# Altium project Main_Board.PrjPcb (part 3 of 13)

## Sheet LTC6952.SchDoc
size A3
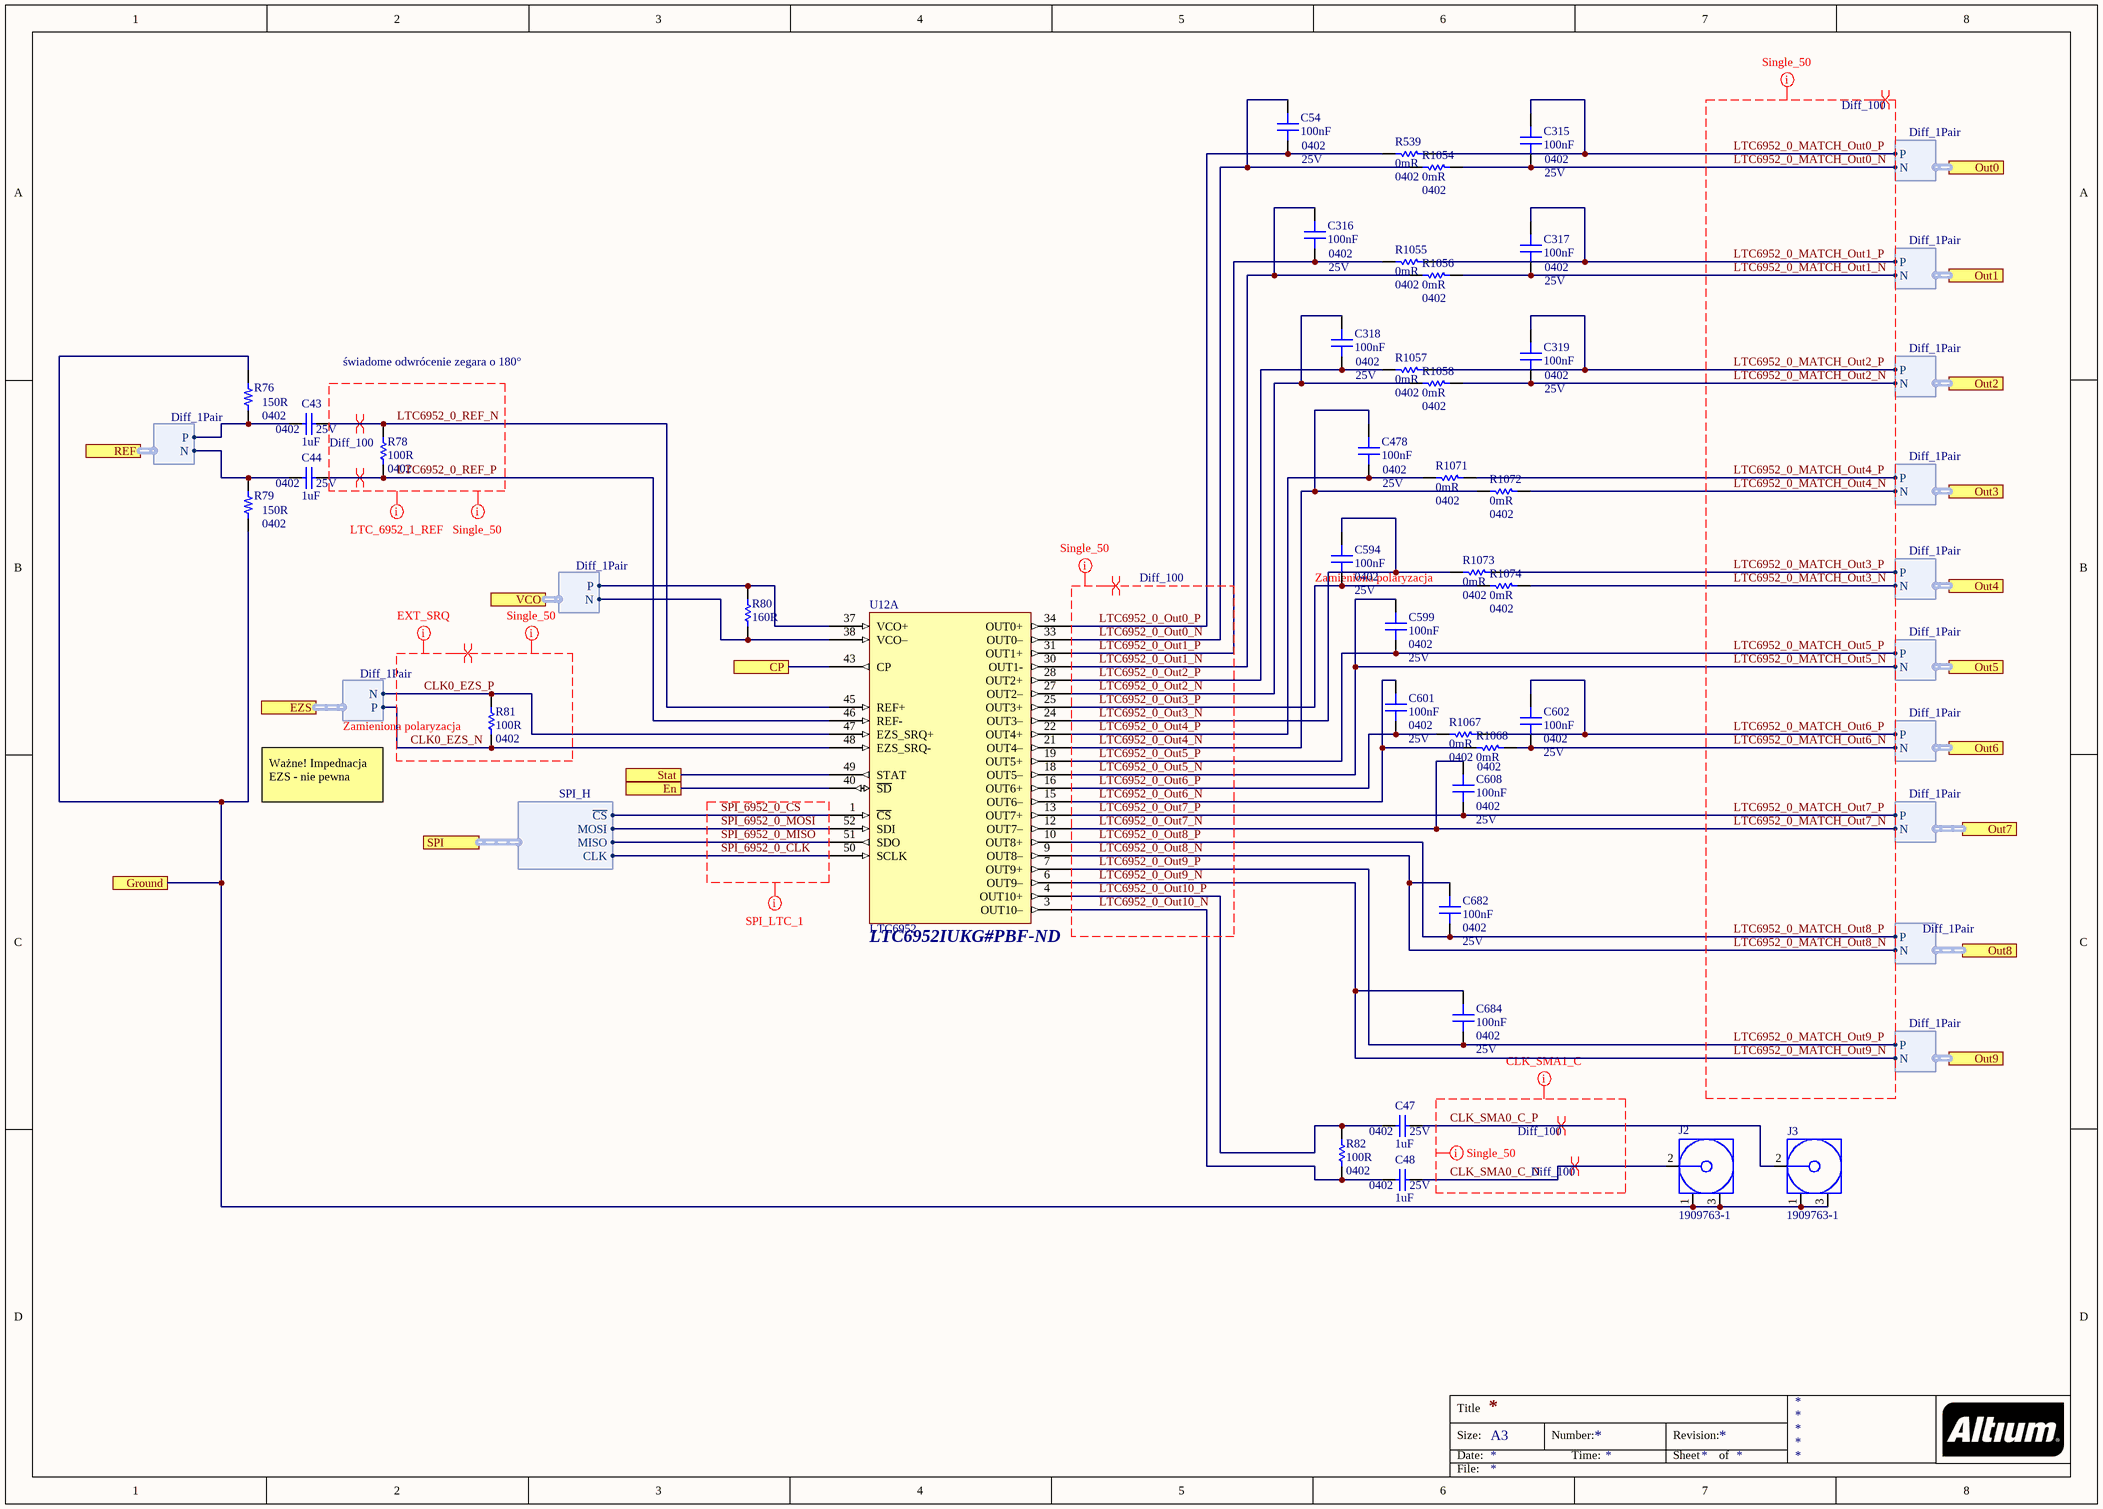
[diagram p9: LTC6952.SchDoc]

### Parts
(Parts that share a designator on the sheet are numbered #1, #2 ... from top to bottom, then left to right.)
C43  1uF  Case/Package: 0402  Voltage Rating: 25V  [CAP 0402/1005 KK]
C44  1uF  Case/Package: 0402  Voltage Rating: 25V  [CAP 0402/1005 KK]
C47  1uF  Case/Package: 0402  Voltage Rating: 25V  [CAP 0402/1005 KK]
C48  1uF  Case/Package: 0402  Voltage Rating: 25V  [CAP 0402/1005 KK]
C54  100nF  Case/Package: 0402  Voltage Rating: 25V  [CAP 0402/1005 KK]
C315  100nF  Case/Package: 0402  Voltage Rating: 25V  [CAP 0402/1005 KK]
C316  100nF  Case/Package: 0402  Voltage Rating: 25V  [CAP 0402/1005 KK]
C317  100nF  Case/Package: 0402  Voltage Rating: 25V  [CAP 0402/1005 KK]
C318  100nF  Case/Package: 0402  Voltage Rating: 25V  [CAP 0402/1005 KK]
C319  100nF  Case/Package: 0402  Voltage Rating: 25V  [CAP 0402/1005 KK]
C478#1  100nF  Case/Package: 0402  Voltage Rating: 25V  [CAP 0402/1005 KK]
C594  100nF  Case/Package: 0402  Voltage Rating: 25V  [CAP 0402/1005 KK]
C599  100nF  Case/Package: 0402  Voltage Rating: 25V  [CAP 0402/1005 KK]
C601  100nF  Case/Package: 0402  Voltage Rating: 25V  [CAP 0402/1005 KK]
C602  100nF  Case/Package: 0402  Voltage Rating: 25V  [CAP 0402/1005 KK]
C608  100nF  Case/Package: 0402  Voltage Rating: 25V  [CAP 0402/1005 KK]
C682  100nF  Case/Package: 0402  Voltage Rating: 25V  [CAP 0402/1005 KK]
C684  100nF  Case/Package: 0402  Voltage Rating: 25V  [CAP 0402/1005 KK]
J2  1909763-1  [TECO-1909763-1_V]
J3  1909763-1  [TECO-1909763-1_V]
R76  150R  Case/Package: 0402  [RES 0402/1005 RF KK]
R78  100R  Case/Package: 0402  [RES 0402/1005 RF KK]
R79  150R  Case/Package: 0402  [RES 0402/1005 RF KK]
R80  160R  [RES 0402/1005 RF KK]
R81  100R  Case/Package: 0402  [RES 0402/1005 RF KK]
R82  100R  Case/Package: 0402  [RES 0402/1005 RF KK]
R539  0mR  Case/Package: 0402  [RES 0402/1005 RF KK]
R1054  0mR  Case/Package: 0402  [RES 0402/1005 RF KK]
R1055  0mR  Case/Package: 0402  [RES 0402/1005 RF KK]
R1056  0mR  Case/Package: 0402  [RES 0402/1005 RF KK]
R1057  0mR  Case/Package: 0402  [RES 0402/1005 RF KK]
R1058  0mR  Case/Package: 0402  [RES 0402/1005 RF KK]
R1067  0mR  Case/Package: 0402  [RES 0402/1005 RF KK]
R1068  0mR  Case/Package: 0402  [RES 0402/1005 RF KK]
R1071  0mR  Case/Package: 0402  [RES 0402/1005 RF KK]
R1072  0mR  Case/Package: 0402  [RES 0402/1005 RF KK]
R1073  0mR  Case/Package: 0402  [RES 0402/1005 RF KK]
R1074  0mR  Case/Package: 0402  [RES 0402/1005 RF KK]
U12  LTC6952  Supplier Part Number 1: LTC6952IUKG#PBF-ND  [LTC6952]  (part A of 2)

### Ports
CP, En, EZS (harness Diff_1Pair), Ground, Out0 (harness Diff_1Pair), Out1 (harness Diff_1Pair), Out2 (harness Diff_1Pair), Out3 (harness Diff_1Pair), Out4 (harness Diff_1Pair), Out5 (harness Diff_1Pair), Out6 (harness Diff_1Pair), Out7 (harness Diff_1Pair), Out8 (harness Diff_1Pair), Out9 (harness Diff_1Pair), REF (harness Diff_1Pair), SPI (harness SPI_H), Stat, VCO (harness Diff_1Pair)

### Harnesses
SPI_H: CLK, MISO, MOSI, ~{CS}
Diff_1Pair: N, P

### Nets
AGND: J2.1 J2.3 J3.1 J3.3 R76.2 R79.1 ; port Ground
CLK0_EZS_N: R81.1 U12.48(EZS_SRQ-) ; port EZS.P
CLK0_EZS_P: R81.2 U12.47(EZS_SRQ+) ; port EZS.N
CLK_SMA0_C_N: C48.1 J2.2
CLK_SMA0_C_P: C47.1 J3.2
Enable_CLK: U12.40(~{SD}) ; port En
LTC6952_0_MATCH_Out0_N: C315.1 R1054.1 ; port Out0.N
LTC6952_0_MATCH_Out0_P: C315.2 R539.1 ; port Out0.P
LTC6952_0_MATCH_Out1_N: C317.1 R1056.1 ; port Out1.N
LTC6952_0_MATCH_Out1_P: C317.2 R1055.1 ; port Out1.P
LTC6952_0_MATCH_Out2_N: C319.1 R1058.1 ; port Out2.N
LTC6952_0_MATCH_Out2_P: C319.2 R1057.1 ; port Out2.P
LTC6952_0_MATCH_Out3_N: R1074.1 ; port Out4.N
LTC6952_0_MATCH_Out3_P: R1073.1 ; port Out4.P
LTC6952_0_MATCH_Out4_N: R1072.2 ; port Out3.N
LTC6952_0_MATCH_Out4_P: R1071.2 ; port Out3.P
LTC6952_0_MATCH_Out5_N: C599.1 U12.18(OUT5–) ; port Out5.N  [also labelled LTC6952_0_Out5_N]
LTC6952_0_MATCH_Out5_P: C599.2 U12.19(OUT5+) ; port Out5.P  [also labelled LTC6952_0_Out5_P]
LTC6952_0_MATCH_Out6_N: C602.2 R1068.1 ; port Out6.N
LTC6952_0_MATCH_Out6_P: C602.1 R1067.1 ; port Out6.P
LTC6952_0_MATCH_Out7_N: C608.1 U12.12(OUT7–) ; port Out7.N  [also labelled LTC6952_0_Out7_N]
LTC6952_0_MATCH_Out7_P: C608.2 U12.13(OUT7+) ; port Out7.P  [also labelled LTC6952_0_Out7_P]
LTC6952_0_MATCH_Out8_N: C682.1 U12.9(OUT8–) ; port Out8.N  [also labelled LTC6952_0_Out8_N]
LTC6952_0_MATCH_Out8_P: C682.2 U12.10(OUT8+) ; port Out8.P  [also labelled LTC6952_0_Out8_P]
LTC6952_0_MATCH_Out9_N: C684.1 U12.6(OUT9–) ; port Out9.N  [also labelled LTC6952_0_Out9_N]
LTC6952_0_MATCH_Out9_P: C684.2 U12.7(OUT9+) ; port Out9.P  [also labelled LTC6952_0_Out9_P]
LTC6952_0_Out0_N: C54.2 R1054.2 U12.33(OUT0–)
LTC6952_0_Out0_P: C54.1 R539.2 U12.34(OUT0+)
LTC6952_0_Out1_N: C316.2 R1056.2 U12.30(OUT1-)
LTC6952_0_Out1_P: C316.1 R1055.2 U12.31(OUT1+)
LTC6952_0_Out2_N: C318.2 R1058.2 U12.27(OUT2–)
LTC6952_0_Out2_P: C318.1 R1057.2 U12.28(OUT2+)
LTC6952_0_Out3_N: C594.1 R1073.2 U12.24(OUT3–)
LTC6952_0_Out3_P: C594.2 R1074.2 U12.25(OUT3+)
LTC6952_0_Out4_N: C478#1.2 R1072.1 U12.21(OUT4–)
LTC6952_0_Out4_P: C478#1.1 R1071.1 U12.22(OUT4+)
LTC6952_0_Out6_N: C601.1 R1068.2 U12.15(OUT6–)
LTC6952_0_Out6_P: C601.2 R1067.2 U12.16(OUT6+)
LTC6952_0_Out10_N: C48.2 R82.1 U12.3(OUT10–)
LTC6952_0_Out10_P: C47.2 R82.2 U12.4(OUT10+)
LTC6952_0_REF_N: C43.1 R78.2 U12.45(REF+)
LTC6952_0_REF_P: C44.1 R78.1 U12.46(REF-)
LTC6952_1_CP_Out: U12.43(CP) ; port CP
LTC6952_1_Temp: U12.49(STAT) ; port Stat
LTC6952_1_VCO_N: R80.2 U12.37(VCO+) ; port VCO.P
LTC6952_1_VCO_P: R80.1 U12.38(VCO–) ; port VCO.N
Si53323_2_Q1_N: C44.2 R79.2 ; port REF.N
Si53323_2_Q1_P: C43.2 R76.1 ; port REF.P
SPI_6952_0_CLK: U12.50(SCLK) ; port SPI.CLK  [project net CLK0_SPI.CLK]
SPI_6952_0_CS: U12.1(~{CS}) ; port SPI.~{CS}  [project net CLK0_SPI.~{CS}]
SPI_6952_0_MISO: U12.51(SDO) ; port SPI.MISO  [project net CLK0_SPI.MISO]
SPI_6952_0_MOSI: U12.52(SDI) ; port SPI.MOSI  [project net CLK0_SPI.MOSI]

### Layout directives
differential pair; differential pair class Diff_100: CLK0_EZS_N, CLK0_EZS_P, CLK_SMA0_C_N, CLK_SMA0_C_P, LTC6952_0_MATCH_Out0_N, LTC6952_0_MATCH_Out0_P, LTC6952_0_MATCH_Out1_N, LTC6952_0_MATCH_Out1_P, LTC6952_0_MATCH_Out2_N, LTC6952_0_MATCH_Out2_P, LTC6952_0_MATCH_Out3_N, LTC6952_0_MATCH_Out3_P, LTC6952_0_MATCH_Out4_N, LTC6952_0_MATCH_Out4_P, LTC6952_0_MATCH_Out5_N, LTC6952_0_MATCH_Out5_P, LTC6952_0_MATCH_Out6_N, LTC6952_0_MATCH_Out6_P, LTC6952_0_MATCH_Out7_N, LTC6952_0_MATCH_Out7_P, LTC6952_0_MATCH_Out8_N, LTC6952_0_MATCH_Out8_P, LTC6952_0_MATCH_Out9_N, LTC6952_0_MATCH_Out9_P, LTC6952_0_Out0_N, LTC6952_0_Out0_P, LTC6952_0_Out1_N, LTC6952_0_Out1_P, LTC6952_0_Out2_N, LTC6952_0_Out2_P, LTC6952_0_Out3_N, LTC6952_0_Out3_P, LTC6952_0_Out4_N, LTC6952_0_Out4_P, LTC6952_0_Out5_N, LTC6952_0_Out5_P, LTC6952_0_Out6_N, LTC6952_0_Out6_P, LTC6952_0_Out7_N, LTC6952_0_Out7_P, LTC6952_0_Out8_N, LTC6952_0_Out8_P, LTC6952_0_Out9_N, LTC6952_0_Out9_P, LTC6952_0_Out10_N, LTC6952_0_Out10_P, LTC6952_0_REF_N, LTC6952_0_REF_P
net class Single_50: CLK0_EZS_N, CLK0_EZS_P, CLK_SMA0_C_N, CLK_SMA0_C_P, LTC6952_0_MATCH_Out0_N, LTC6952_0_MATCH_Out0_P, LTC6952_0_MATCH_Out1_N, LTC6952_0_MATCH_Out1_P, LTC6952_0_MATCH_Out2_N, LTC6952_0_MATCH_Out2_P, LTC6952_0_MATCH_Out3_N, LTC6952_0_MATCH_Out3_P, LTC6952_0_MATCH_Out4_N, LTC6952_0_MATCH_Out4_P, LTC6952_0_MATCH_Out5_N, LTC6952_0_MATCH_Out5_P, LTC6952_0_MATCH_Out6_N, LTC6952_0_MATCH_Out6_P, LTC6952_0_MATCH_Out7_N, LTC6952_0_MATCH_Out7_P, LTC6952_0_MATCH_Out8_N, LTC6952_0_MATCH_Out8_P, LTC6952_0_MATCH_Out9_N, LTC6952_0_MATCH_Out9_P, LTC6952_0_Out0_N, LTC6952_0_Out0_P, LTC6952_0_Out1_N, LTC6952_0_Out1_P, LTC6952_0_Out2_N, LTC6952_0_Out2_P, LTC6952_0_Out3_N, LTC6952_0_Out3_P, LTC6952_0_Out4_N, LTC6952_0_Out4_P, LTC6952_0_Out5_N, LTC6952_0_Out5_P, LTC6952_0_Out6_N, LTC6952_0_Out6_P, LTC6952_0_Out7_N, LTC6952_0_Out7_P, LTC6952_0_Out8_N, LTC6952_0_Out8_P, LTC6952_0_Out9_N, LTC6952_0_Out9_P, LTC6952_0_Out10_N, LTC6952_0_Out10_P, LTC6952_0_REF_N, LTC6952_0_REF_P
net class CLK_SMA1_C: CLK_SMA0_C_N, CLK_SMA0_C_P
net class LTC_6952_1_REF: LTC6952_0_REF_N, LTC6952_0_REF_P
net class EXT_SRQ: CLK0_EZS_N, CLK0_EZS_P
net class SPI_LTC_1: SPI_6952_0_CLK, SPI_6952_0_CS, SPI_6952_0_MISO, SPI_6952_0_MOSI

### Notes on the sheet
- świadome odwrócenie zegara o 180°
- (near C594) Zamieniona polaryzacja
- (near R81) Zamieniona polaryzacja
- Ważne! Impednacja EZS - nie pewna

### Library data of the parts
C43 C44 C47 C48 = Capacitor: MURATA - GRT155R61E105KE01D - SMD Multilayer Ceramic Capacitor, 1 µF, 25 V, 0402 [1005 Metric], ± 10%, X5R, GRT Series - SMD Multilayer Ceramic Capacitor, 1 µF, 25 V, 0402 [1005 Metric], ± 10%, X5R, GRT Series
C54 C315-C319 C478#1 C594 C599 C601 C602 C608 C682 C684 = Capacitor: Manufacturer: Murata; Manufacturer Part Number: GRM155R71E104KE14J; Tolerance: 10%; Dielectric: X7R
J2 J3 = 1909763-1: Ultra Miniature Coaxial Connector Jack, 60 V, 50 Ohm, -40 to 90 degC, RoHS, Tape and Reel; Brand: TE Connectivity / AMP; Maximum Frequency: 6 GHz; Gender: Jack (Female); Body Material: Liquid Crystal Polymer (LCP); RF Series: UMCC; Impedance: 50 Ohms
R76 R79 = Resistor: RES SMD 150 OHM 1% 1/10W 0402; Manufacturer: Panasonic; Manufacturer Part Number: ERJ-2RKF1500X; Temperature Coefficient: 100ppm/°C; Power Rating: 100mW; Voltage Rating: 50V
R78 R81 R82 = Resistor: RES SMD 100 OHM 1% 1/16W 0402; Manufacturer: Yageo; Manufacturer Part Number: RC0402FR-07100RL; Power Rating: 62.5mW; Voltage Rating: 50V; Temperature Coefficient: 100ppm/°C
R80 = Resistor: Res Thick Film 0402 160 Ohm 1% 1/16W 100ppm/C Molded SMD SMD Paper T/R; Manufacturer: Stackpole Electronics; Manufacturer Part Number: RMCF0402FT160R; Temperature Coefficient: 100ppm/°C
R539 R1054-R1058 R1067 R1068 R1071-R1074 = Resistor: Manufacturer 1: Yageo; Manufacturer Part Number 1: RC0402JR-070RL; Power Rating: 62.5mW; Tolerance: 5%; Voltage Rating: 50V; Max Power Dissipation: 63mW; Temperature Coefficient: 200ppm/°C
U12 = LTC6952: Dystrybutor Zegarów; Manufacturer: Analog Devices; Manufacturer Part Number: LTC6952IUKG#PBF

## Sheet Ultrascale+_02.SchDoc: Ultrascale+_02
size A3; Organization: Altium Limited; Address1: L3, 12a Rodborough Rd; Address2: Frenchs Forest; Address3: NSW; Address4: Australia 2086
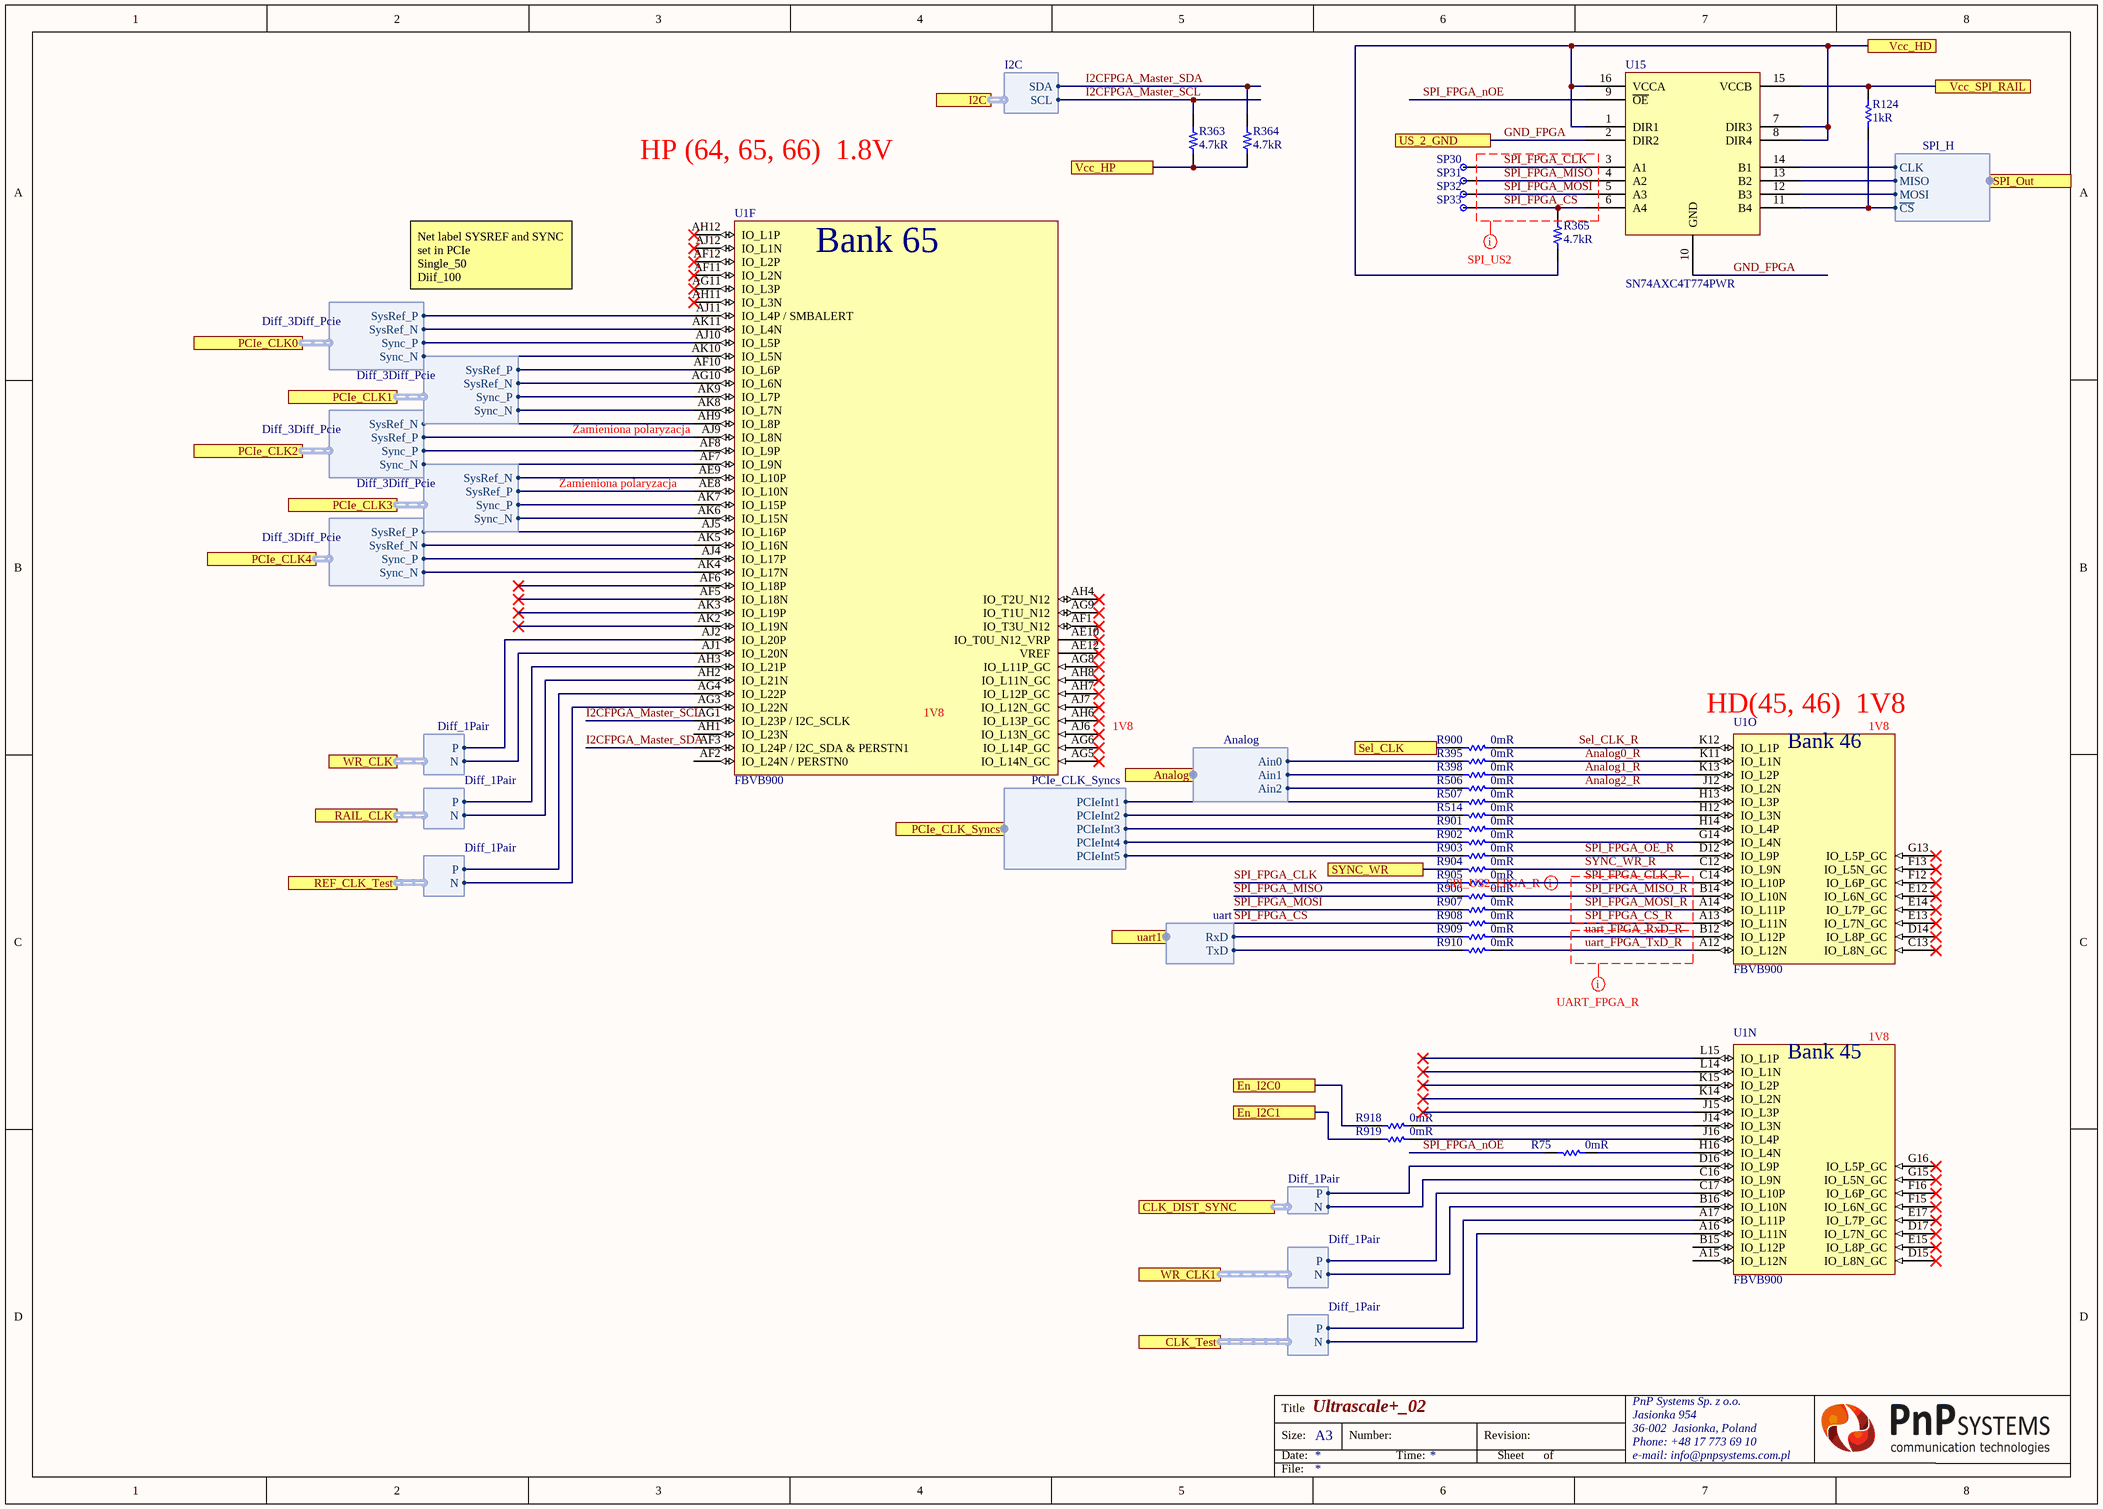
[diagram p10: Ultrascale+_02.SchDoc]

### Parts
R75  0mR  [RES 0402/1005 RF KK]
R124  1kR  [RES 0402/1005 RF KK]
R363  4.7kR  [RES 0402/1005 RF KK]
R364  4.7kR  [RES 0402/1005 RF KK]
R365  4.7kR  [RES 0402/1005 RF KK]
R395  0mR  [RES 0402/1005 RF KK]
R398  0mR  [RES 0402/1005 RF KK]
R506  0mR  [RES 0402/1005 RF KK]
R507  0mR  [RES 0402/1005 RF KK]
R514  0mR  [RES 0402/1005 RF KK]
R900  0mR  [RES 0402/1005 RF KK]
R901  0mR  [RES 0402/1005 RF KK]
R902  0mR  [RES 0402/1005 RF KK]
R903  0mR  [RES 0402/1005 RF KK]
R904  0mR  [RES 0402/1005 RF KK]
R905  0mR  [RES 0402/1005 RF KK]
R906  0mR  [RES 0402/1005 RF KK]
R907  0mR  [RES 0402/1005 RF KK]
R908  0mR  [RES 0402/1005 RF KK]
R909  0mR  [RES 0402/1005 RF KK]
R910  0mR  [RES 0402/1005 RF KK]
R918  0mR  [RES 0402/1005 RF KK]
R919  0mR  [RES 0402/1005 RF KK]
SP30  SP  [MeasureTP]  (value not drawn)
SP31  SP  [MeasureTP]  (value not drawn)
SP32  SP  [MeasureTP]  (value not drawn)
SP33  SP  [MeasureTP]  (value not drawn)
U1  FBVB900  [FBVB900 XX]  (parts F,N,O of 23)
U15  SN74AXC4T774PWR  [SN74AXC4T774PWR]

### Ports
Analog (harness Analog), CLK_DIST_SYNC (harness Diff_1Pair), CLK_Test (harness Diff_1Pair), En_I2C0, En_I2C1, I2C (harness I2C), PCIe_CLK0 (harness Diff_3Diff_Pcie), PCIe_CLK1 (harness Diff_3Diff_Pcie), PCIe_CLK2 (harness Diff_3Diff_Pcie), PCIe_CLK3 (harness Diff_3Diff_Pcie), PCIe_CLK4 (harness Diff_3Diff_Pcie), PCIe_CLK_Syncs (harness PCIe_CLK_Syncs), RAIL_CLK (harness Diff_1Pair), REF_CLK_Test (harness Diff_1Pair), Sel_CLK, SPI_Out (harness SPI_H), SYNC_WR, uart1 (harness uart), US_2_GND, Vcc_HD, Vcc_HP, Vcc_SPI_RAIL, WR_CLK1 (harness Diff_1Pair), WR_CLK (harness Diff_1Pair)

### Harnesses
I2C: SDA, SCL
uart: RxD, TxD
Diff_1Pair: N, P
Diff_1Pair: P, N
SPI_H: CLK, MISO, MOSI, ~{CS}
Analog: Ain0, Ain1, Ain2
PCIe_CLK_Syncs: PCIeInt1, PCIeInt2, PCIeInt3, PCIeInt4, PCIeInt5
Diff_3Diff_Pcie: SysRef_N, SysRef_P, Sync_P, Sync_N

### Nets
GND_FPGA: U15.2(DIR2) U15.10(GND) ; port US_2_GND  [project net B503_Ground]
3V3_RAIL: R124.2 U15.15(VCCB) ; port Vcc_SPI_RAIL
Analog0_R: R395.1 U1.K11(IO_L1N)
Analog1_R: R398.1 U1.K13(IO_L2P)
Analog2_R: R506.1 U1.J12(IO_L2N)
CLK0_EZS_N: U1.D16(IO_L9P) ; port CLK_DIST_SYNC.P
CLK0_EZS_P: U1.C16(IO_L9N) ; port CLK_DIST_SYNC.N
D_05028_G0: R904.2 ; port SYNC_WR
I2CFPGA_Master_SCL: R363.2 U1.AG1(IO_L23P_/_I2C_SCLK) ; port I2C.SCL  [project net I2C_LS.SCL]
I2CFPGA_Master_SDA: R364.2 U1.AF3(IO_L24P_/_I2C_SDA_&_PERSTN1) ; port I2C.SDA  [project net I2C_LS.SDA]
LTC6952_1_MATCH_Out1_N: U1.AH2(IO_L21N) ; port RAIL_CLK.N
LTC6952_1_MATCH_Out1_P: U1.AH3(IO_L21P) ; port RAIL_CLK.P
LTC6952_1_Temp: R395.2 ; port Analog.Ain0
LTC6952_2_Temp: R398.2 ; port Analog.Ain1
LTC6952_3_Temp: R506.2 ; port Analog.Ain2
RF_SYSREF_TO_FPGA_N: U1.AK11(IO_L4N) ; port PCIe_CLK0.SysRef_N
RF_SYSREF_TO_FPGA_N: U1.AG10(IO_L6N) ; port PCIe_CLK1.SysRef_N  [a separate net that carries the same name]
RF_SYSREF_TO_FPGA_N: U1.AH9(IO_L8P) ; port PCIe_CLK2.SysRef_N  [a separate net that carries the same name]
RF_SYSREF_TO_FPGA_N: U1.AE9(IO_L10P) ; port PCIe_CLK3.SysRef_N  [a separate net that carries the same name]
RF_SYSREF_TO_FPGA_N: U1.AK5(IO_L16N) ; port PCIe_CLK4.SysRef_N  [a separate net that carries the same name]
RF_SYSREF_TO_FPGA_P: U1.AJ11(IO_L4P_/_SMBALERT) ; port PCIe_CLK0.SysRef_P
RF_SYSREF_TO_FPGA_P: U1.AF10(IO_L6P) ; port PCIe_CLK1.SysRef_P  [a separate net that carries the same name]
RF_SYSREF_TO_FPGA_P: U1.AJ9(IO_L8N) ; port PCIe_CLK2.SysRef_P  [a separate net that carries the same name]
RF_SYSREF_TO_FPGA_P: U1.AE8(IO_L10N) ; port PCIe_CLK3.SysRef_P  [a separate net that carries the same name]
RF_SYSREF_TO_FPGA_P: U1.AJ5(IO_L16P) ; port PCIe_CLK4.SysRef_P  [a separate net that carries the same name]
Sel_CLK_R: R900.1 U1.K12(IO_L1P)
SetClk_Si53323_2: R900.2 ; port Sel_CLK
Si53323_1_Q2_LVDS_N: U1.AG3(IO_L22N) ; port REF_CLK_Test.N
Si53323_1_Q2_LVDS_P: U1.AG4(IO_L22P) ; port REF_CLK_Test.P
Si53323_2_Q2_LVDS_N: U1.A16(IO_L11N) ; port CLK_Test.N
Si53323_2_Q2_LVDS_P: U1.A17(IO_L11P) ; port CLK_Test.P
SPI1_CLK: U15.14(B1) ; port SPI_Out.CLK
SPI1_CS: R124.1 U15.11(B4) ; port SPI_Out.~{CS}
SPI1_MISO: U15.13(B2) ; port SPI_Out.MISO
SPI1_MOSI: U15.12(B3) ; port SPI_Out.MOSI
SPI_FPGA_CLK: R905.2 SP30.1 U15.3(A1)
SPI_FPGA_CLK_R: R905.1 U1.C14(IO_L10P)
SPI_FPGA_CS: R365.2 R908.2 SP33.1 U15.6(A4)
SPI_FPGA_CS_R: R908.1 U1.A13(IO_L11N)
SPI_FPGA_MISO: R906.2 SP31.1 U15.4(A2)
SPI_FPGA_MISO_R: R906.1 U1.B14(IO_L10N)
SPI_FPGA_MOSI: R907.2 SP32.1 U15.5(A3)
SPI_FPGA_MOSI_R: R907.1 U1.A14(IO_L11P)
SPI_FPGA_nOE: R75.2 U15.9(~{OE})
SPI_FPGA_OE_R: R903.1 U1.D12(IO_L9P)
SYNC_N: U1.AK10(IO_L5N) ; port PCIe_CLK0.Sync_N
SYNC_N: U1.AK8(IO_L7N) ; port PCIe_CLK1.Sync_N  [a separate net that carries the same name]
SYNC_N: U1.AF7(IO_L9N) ; port PCIe_CLK2.Sync_N  [a separate net that carries the same name]
SYNC_N: U1.AK6(IO_L15N) ; port PCIe_CLK3.Sync_N  [a separate net that carries the same name]
SYNC_N: U1.AK4(IO_L17N) ; port PCIe_CLK4.Sync_N  [a separate net that carries the same name]
SYNC_P: U1.AJ10(IO_L5P) ; port PCIe_CLK0.Sync_P
SYNC_P: U1.AK9(IO_L7P) ; port PCIe_CLK1.Sync_P  [a separate net that carries the same name]
SYNC_P: U1.AF8(IO_L9P) ; port PCIe_CLK2.Sync_P  [a separate net that carries the same name]
SYNC_P: U1.AK7(IO_L15P) ; port PCIe_CLK3.Sync_P  [a separate net that carries the same name]
SYNC_P: U1.AJ4(IO_L17P) ; port PCIe_CLK4.Sync_P  [a separate net that carries the same name]
SYNC_WR_R: R904.1 U1.C12(IO_L9N)
uart_FPGA_RxD_R: R909.1 U1.B12(IO_L12P)
uart_FPGA_TxD_R: R910.1 U1.A12(IO_L12N)
US2_FTDI_UART1_RXD: R910.2 ; port uart1.TxD
US2_FTDI_UART1_TXD: R909.2 ; port uart1.RxD
US+_MGTVccAux: R363.1 R364.1 R365.1 U15.1(DIR1) U15.7(DIR3) U15.8(DIR4) U15.16(VCCA) ; port Vcc_HP, port Vcc_HD
WR_LMK_CLK_RC_HF1_N: U1.AJ1(IO_L20N) ; port WR_CLK.N
WR_LMK_CLK_RC_HF1_P: U1.AJ2(IO_L20P) ; port WR_CLK.P
WR_LMK_CLK_RC_HF2_N: U1.C17(IO_L10P) ; port WR_CLK1.P
WR_LMK_CLK_RC_HF2_P: U1.B16(IO_L10N) ; port WR_CLK1.N
NetJ1_PCIE0_20: R507.2 ; port PCIe_CLK_Syncs.PCIeInt1
NetJ1_PCIE1_20: R514.2 ; port PCIe_CLK_Syncs.PCIeInt2
NetJ1_PCIE2_20: R901.2 ; port PCIe_CLK_Syncs.PCIeInt3
NetJ1_PCIE3_20: R902.2 ; port PCIe_CLK_Syncs.PCIeInt4
NetJ1_PCIE4_20: R903.2 ; port PCIe_CLK_Syncs.PCIeInt5
NetR75_1: R75.1 U1.H16(IO_L4N)
NetR507_1: R507.1 U1.H13(IO_L3P)
NetR514_1: R514.1 U1.H12(IO_L3N)
NetR901_1: R901.1 U1.H14(IO_L4P)
NetR902_1: R902.1 U1.G14(IO_L4N)
NetR918_1: R918.1 U1.J14(IO_L3N)
NetR918_2: R918.2 ; port En_I2C0
NetR919_1: R919.1 U1.J16(IO_L4P)
NetR919_2: R919.2 ; port En_I2C1

Not connected (* = marked no-connect by the designer): U1 A15(IO_L12N) AE10(IO_T0U_N12_VRP)* AE12(VREF)* AF1(IO_T3U_N12)* AF2(IO_L24N_/_PERSTN0) AF5(IO_L18N)* AF6(IO_L18P)* AF11(IO_L2N)* AF12(IO_L2P)* AG5(IO_L14N_GC)* AG6(IO_L14P_GC)* AG8(IO_L11P_GC)* AG9(IO_T1U_N12)* AG11(IO_L3P)* AH1(IO_L23N) AH4(IO_T2U_N12)* AH6(IO_L13P_GC)* AH7(IO_L12P_GC)* AH8(IO_L11N_GC)* AH11(IO_L3N)* AH12(IO_L1P)* AJ6(IO_L13N_GC)* AJ7(IO_L12N_GC)* AJ12(IO_L1N)* AK2(IO_L19N)* AK3(IO_L19P)* B15(IO_L12P) C13(IO_L8N_GC)* D14(IO_L8P_GC)* D15(IO_L8N_GC)* D17(IO_L7N_GC)* E12(IO_L6N_GC)* E13(IO_L7N_GC)* E14(IO_L7P_GC)* E15(IO_L8P_GC)* E17(IO_L7P_GC)* F12(IO_L6P_GC)* F13(IO_L5N_GC)* F15(IO_L6N_GC)* F16(IO_L6P_GC)* G13(IO_L5P_GC)* G15(IO_L5N_GC)* G16(IO_L5P_GC)* J15(IO_L3P)* K14(IO_L2N)* K15(IO_L2P)* L14(IO_L1N)* L15(IO_L1P)*

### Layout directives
net class SPI_US2_R: SPI_FPGA_CLK, SPI_FPGA_CS, SPI_FPGA_MISO, SPI_FPGA_MOSI
net class SPI_US2_FPGA_R: SPI_FPGA_CLK_R
net class UART_FPGA_R: uart_FPGA_RxD_R, uart_FPGA_TxD_R

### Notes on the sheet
- HP (64, 65, 66)  1.8V
- Net label SYSREF and SYNC set in PCIe
  Single_50
  Diif_100
- (near U1) Zamieniona polaryzacja
- (near U1) 1V8
- (near U1) HD(45, 46)  1V8
- 1V8

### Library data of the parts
R75 R395 R398 R506 R507 R514 R900-R910 R918 R919 = Resistor: as R539 on sheet LTC6952
R124 = Resistor: PANASONIC - ERJ-2RKF1001X - SMD Chip Resistor, 0402 [1005 Metric], 1 kohm, ERJ2R Series, 50 V, Thick Film, 100 mW; Temperature Coefficient: 100ppm/°C; Tolerance: 1%; Voltage Rating (DC): 50V; Power Rating: 100mW
R363-R365 = Resistor: Manufacturer: Panasonic; Manufacturer Part Number: ERJ-2RKF4701X; Tolerance: 1%; Temperature Coefficient: 100ppm/°C; Power Rating: 100mW; Voltage Rating: 50V
U1 = FBVB900: FPGA Zynq UltraScale+ Family 192150 Cells 20nm Technology 0.85V 900-Pin FCBGA Tray; Manufacturer Part Number: XCZU4CG-1FBVB900E; Manufacturer: Xilinx; Peripherals: WDT,DMA; Interface: I2C,SPI,USB,Ethernet,MMC,SDIO,SD,UART,USART,EBI/EMI; Core Architecture: ARM; RAM Size: 256KB; Frequency: 500MHz; Number of I/Os: 204
U15 = SN74AXC4T774PWR: Manufacturer 1: Texas Instruments

## Sheet JESD204_B_or_C.SchDoc: JESD204_B
size A3; Organization: Altium Limited; Address1: L3, 12a Rodborough Rd; Address2: Frenchs Forest; Address3: NSW; Address4: Australia 2086
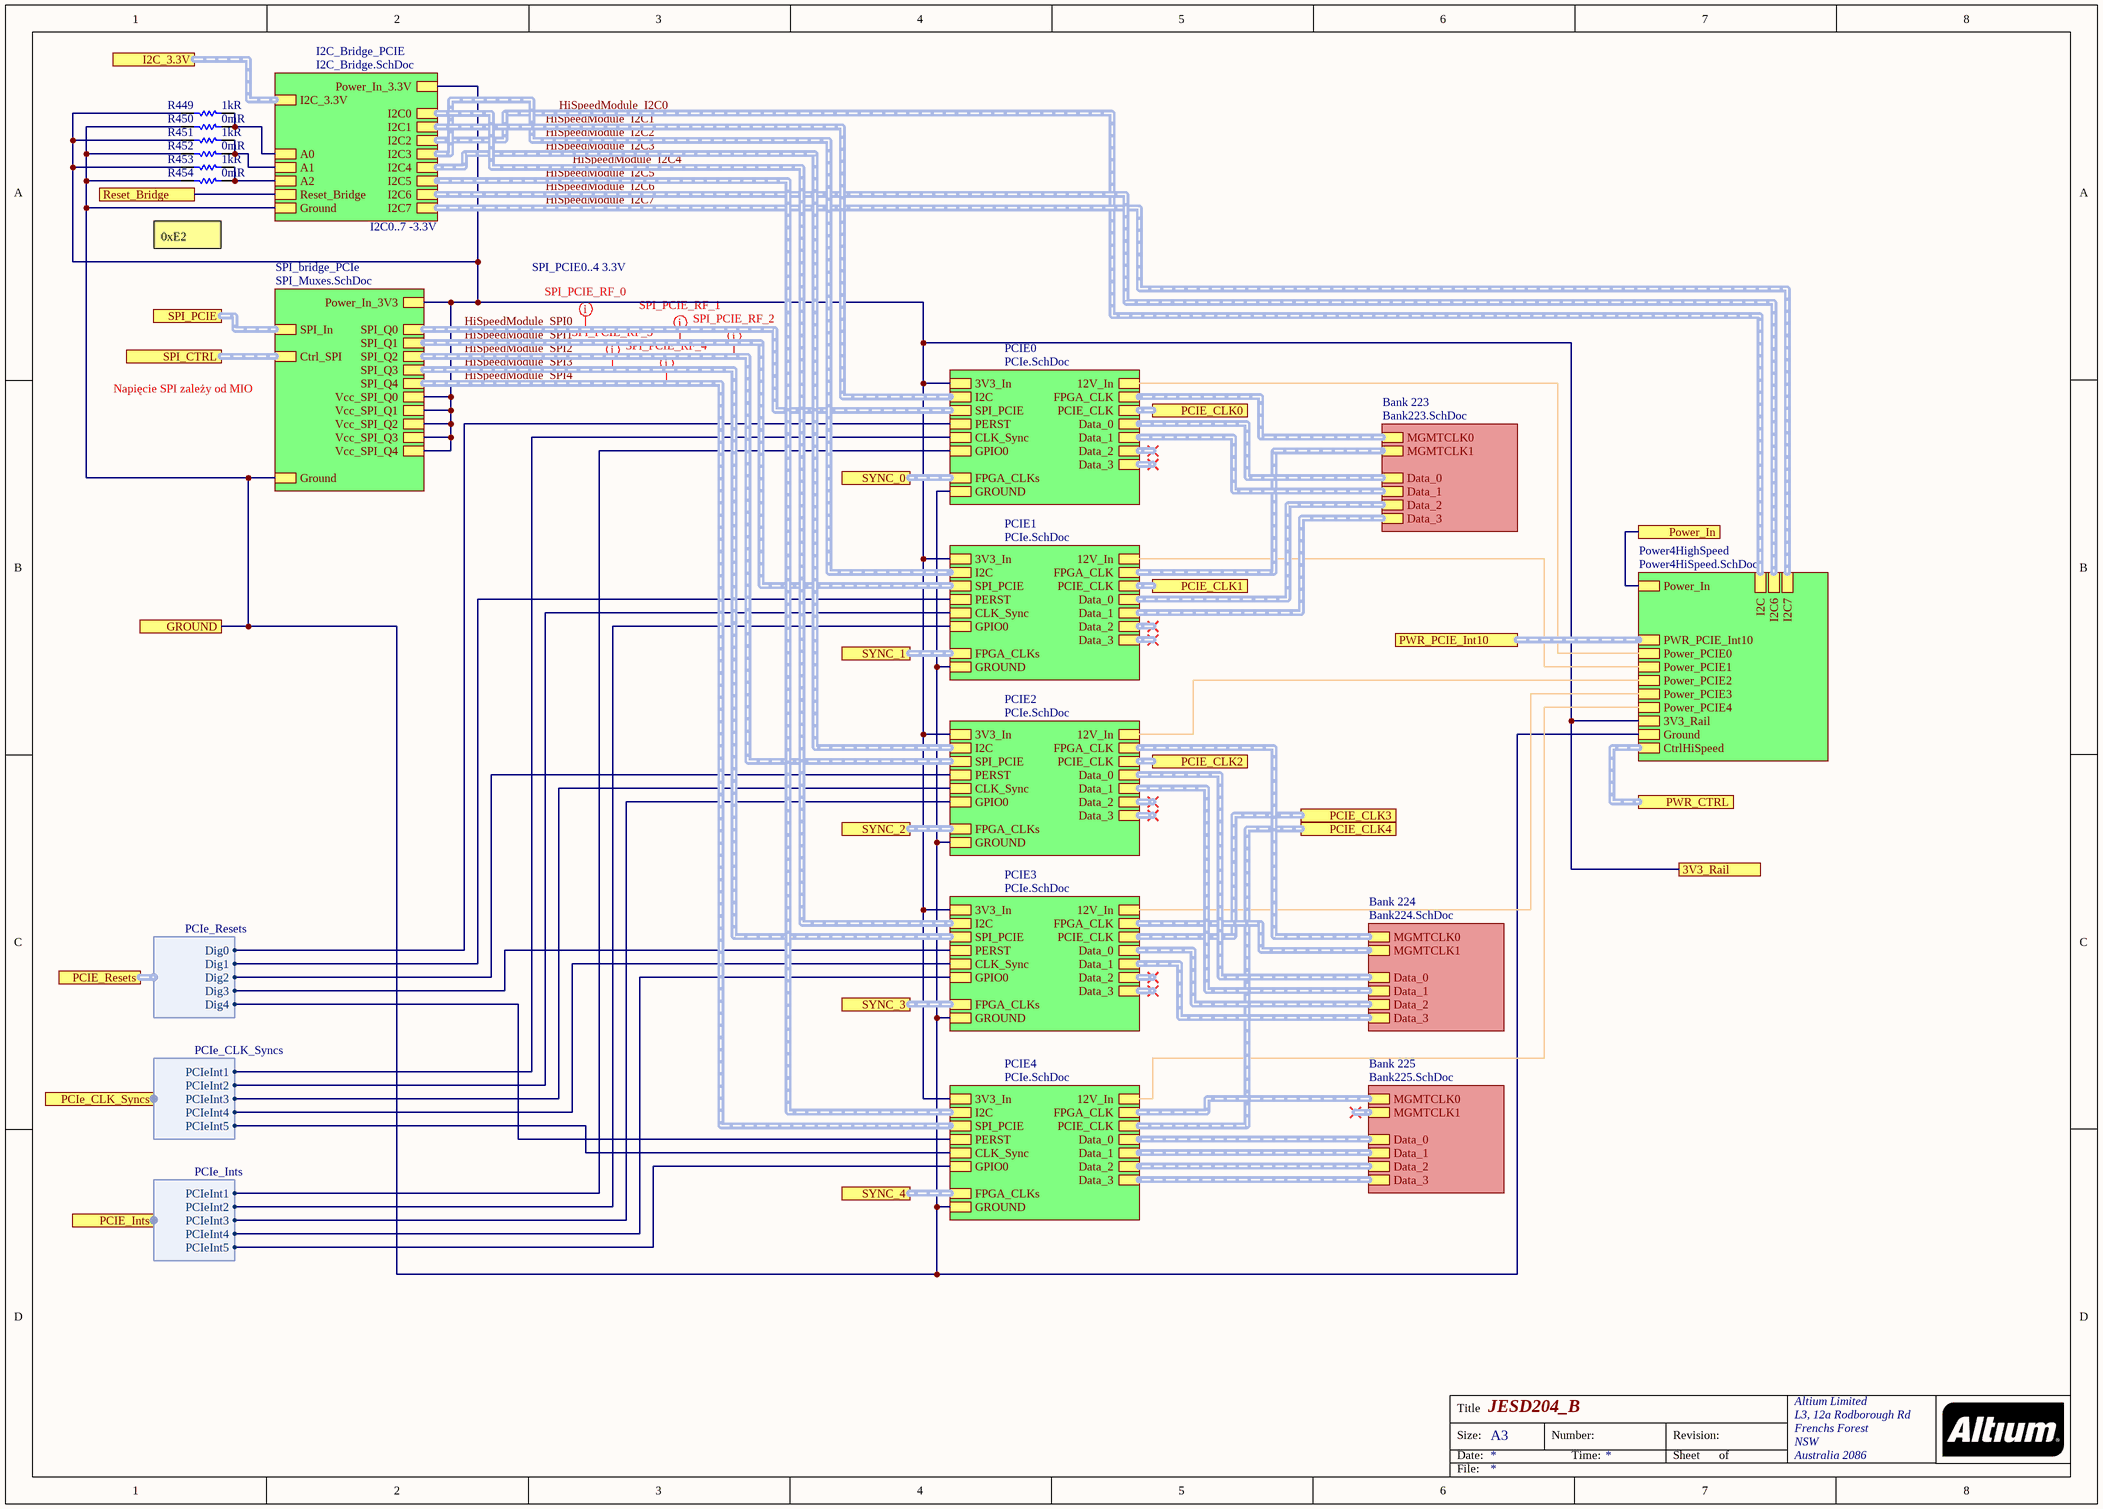
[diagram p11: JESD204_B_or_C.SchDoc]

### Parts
R449  1kR  [RES 0402/1005 RF KK]
R450  0mR  [RES 0402/1005 RF KK]
R451  1kR  [RES 0402/1005 RF KK]
R452  0mR  [RES 0402/1005 RF KK]
R453  1kR  [RES 0402/1005 RF KK]
R454  0mR  [RES 0402/1005 RF KK]

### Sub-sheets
Bank 223 = Bank223.SchDoc: MGMTCLK0 (harness Diff_1Pair), MGMTCLK1 (harness Diff_1Pair), Data_3 (harness Diff_2PairData), Data_2 (harness Diff_2PairData), Data_1 (harness Diff_2PairData), Data_0 (harness Diff_2PairData)
Bank 224 = Bank224.SchDoc: MGMTCLK0 (harness Diff_1Pair), MGMTCLK1 (harness Diff_1Pair), Data_3 (harness Diff_2PairData), Data_2 (harness Diff_2PairData), Data_1 (harness Diff_2PairData), Data_0 (harness Diff_2PairData)
Bank 225 = Bank225.SchDoc: Data_3 (harness Diff_2PairData), MGMTCLK0 (harness Diff_1Pair), Data_2 (harness Diff_2PairData), Data_1 (harness Diff_2PairData), Data_0 (harness Diff_2PairData), MGMTCLK1 (harness Diff_1Pair)
I2C_Bridge_PCIE = I2C_Bridge.SchDoc: I2C0 (harness I2C), I2C1 (harness I2C), I2C2 (harness I2C), I2C3 (harness I2C), I2C4 (harness I2C), I2C5 (harness I2C), I2C6 (harness I2C), I2C7 (harness I2C), Ground, A2, A1, A0, I2C_3.3V (harness I2C), Reset_Bridge, Power_In_3.3V
PCIE0 = PCIe.SchDoc: 12V_In, I2C (harness I2C), PERST, Data_0 (harness Diff_2PairData), Data_1 (harness Diff_2PairData), Data_2 (harness Diff_2PairData), Data_3 (harness Diff_2PairData), SPI_PCIE (harness SPI_H), 3V3_In, GROUND, FPGA_CLKs (harness Diff_3Diff_Pcie), PCIE_CLK (harness Diff_1Pair), CLK_Sync, GPIO0, FPGA_CLK (harness Diff_1Pair)
PCIE1 = PCIe.SchDoc: 12V_In, I2C (harness I2C), PCIE_CLK (harness Diff_1Pair), PERST, Data_0 (harness Diff_2PairData), Data_1 (harness Diff_2PairData), Data_2 (harness Diff_2PairData), Data_3 (harness Diff_2PairData), SPI_PCIE (harness SPI_H), 3V3_In, GROUND, FPGA_CLKs (harness Diff_3Diff_Pcie), CLK_Sync, GPIO0, FPGA_CLK (harness Diff_1Pair)
PCIE2 = PCIe.SchDoc: 12V_In, I2C (harness I2C), PCIE_CLK (harness Diff_1Pair), PERST, Data_0 (harness Diff_2PairData), Data_1 (harness Diff_2PairData), Data_2 (harness Diff_2PairData), Data_3 (harness Diff_2PairData), SPI_PCIE (harness SPI_H), 3V3_In, GROUND, FPGA_CLKs (harness Diff_3Diff_Pcie), CLK_Sync, GPIO0, FPGA_CLK (harness Diff_1Pair)
PCIE3 = PCIe.SchDoc: 12V_In, I2C (harness I2C), PCIE_CLK (harness Diff_1Pair), PERST, Data_0 (harness Diff_2PairData), Data_1 (harness Diff_2PairData), Data_2 (harness Diff_2PairData), Data_3 (harness Diff_2PairData), SPI_PCIE (harness SPI_H), 3V3_In, GROUND, FPGA_CLKs (harness Diff_3Diff_Pcie), CLK_Sync, GPIO0, FPGA_CLK (harness Diff_1Pair)
PCIE4 = PCIe.SchDoc: 12V_In, I2C (harness I2C), PCIE_CLK (harness Diff_1Pair), PERST, Data_0 (harness Diff_2PairData), Data_1 (harness Diff_2PairData), Data_2 (harness Diff_2PairData), Data_3 (harness Diff_2PairData), SPI_PCIE (harness SPI_H), 3V3_In, FPGA_CLKs (harness Diff_3Diff_Pcie), GROUND, CLK_Sync, GPIO0, FPGA_CLK (harness Diff_1Pair)
Power4HighSpeed = Power4HiSpeed.SchDoc: Power_In, Power_PCIE0, Power_PCIE1, Power_PCIE2, Power_PCIE3, Power_PCIE4, CtrlHiSpeed (harness Ctrl_Pwr4HiSpeed), Ground, I2C (harness I2C), 3V3_Rail, PWR_PCIE_Int10 (harness PWR_PCIE_Int10), I2C6, I2C7
SPI_bridge_PCIe = SPI_Muxes.SchDoc: SPI_Q0 (harness SPI_H), SPI_Q1 (harness SPI_H), SPI_Q2 (harness SPI_H), SPI_Q3 (harness SPI_H), SPI_Q4 (harness SPI_H), SPI_In (harness SPI_H), Power_In_3V3, Ctrl_SPI (harness Ctrl_SPI_PCIE), Vcc_SPI_Q4, Vcc_SPI_Q3, Vcc_SPI_Q2, Vcc_SPI_Q1, Vcc_SPI_Q0, Ground

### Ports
3V3_Rail, GROUND, I2C_3.3V (harness I2C), PCIE_CLK0 (harness Diff_1Pair), PCIE_CLK1 (harness Diff_1Pair), PCIE_CLK2 (harness Diff_1Pair), PCIE_CLK3 (harness Diff_1Pair), PCIE_CLK4 (harness Diff_1Pair), PCIe_CLK_Syncs (harness PCIe_CLK_Syncs), PCIE_Ints (harness PCIe_Ints), PCIE_Resets (harness PCIe_Resets), Power_In, PWR_CTRL (harness Ctrl_Pwr4HiSpeed), PWR_PCIE_Int10 (harness PWR_PCIE_Int10), Reset_Bridge, SPI_CTRL (harness Ctrl_SPI_PCIE), SPI_PCIE (harness SPI_H), SYNC_0 (harness Diff_3Diff_Pcie), SYNC_1 (harness Diff_3Diff_Pcie), SYNC_2 (harness Diff_3Diff_Pcie), SYNC_3 (harness Diff_3Diff_Pcie), SYNC_4 (harness Diff_3Diff_Pcie)

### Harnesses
PCIe_Resets: Dig0, Dig1, Dig2, Dig3, Dig4
PCIe_CLK_Syncs: PCIeInt1, PCIeInt2, PCIeInt3, PCIeInt4, PCIeInt5
PCIe_Ints: PCIeInt1, PCIeInt2, PCIeInt3, PCIeInt4, PCIeInt5

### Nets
B503_Ground: R450.2 R452.2 R454.2 ; port GROUND, sheet PCIE0/GROUND, sheet PCIE1/GROUND, sheet PCIE2/GROUND, sheet PCIE3/GROUND, sheet PCIE4/GROUND, sheet I2C_Bridge_PCIE/Ground, sheet SPI_bridge_PCIe/Ground, sheet Power4HighSpeed/Ground
3V3_RAIL: R449.1 R451.1 R453.1 ; port 3V3_Rail, sheet PCIE0/3V3_In, sheet PCIE1/3V3_In, sheet PCIE2/3V3_In, sheet PCIE3/3V3_In, sheet PCIE4/3V3_In, sheet I2C_Bridge_PCIE/Power_In_3.3V, sheet SPI_bridge_PCIe/Power_In_3V3, sheet SPI_bridge_PCIe/Vcc_SPI_Q4, sheet SPI_bridge_PCIe/Vcc_SPI_Q3, sheet SPI_bridge_PCIe/Vcc_SPI_Q2, sheet SPI_bridge_PCIe/Vcc_SPI_Q1, sheet SPI_bridge_PCIe/Vcc_SPI_Q0, sheet Power4HighSpeed/3V3_Rail
12V_LT3042: port Power_In, sheet Power4HighSpeed/Power_In
12V_PCIE0_CM: sheet PCIE0/12V_In, sheet Power4HighSpeed/Power_PCIE0
12V_PCIE1_CM: sheet PCIE1/12V_In, sheet Power4HighSpeed/Power_PCIE1
12V_PCIE2_CM: sheet PCIE2/12V_In, sheet Power4HighSpeed/Power_PCIE2
12V_PCIE3_CM: sheet PCIE3/12V_In, sheet Power4HighSpeed/Power_PCIE3
12V_PCIE4_CM: sheet PCIE4/12V_In, sheet Power4HighSpeed/Power_PCIE4
GPIOa_02.GPIO0: sheet PCIE0/PERST, port PCIE_Resets.Dig0
GPIOa_11.GPIO1: sheet PCIE1/PERST, port PCIE_Resets.Dig1
GPIOb_02.GPIO0: port Reset_Bridge, sheet I2C_Bridge_PCIE/Reset_Bridge
GPIOb_02.GPIO2: sheet PCIE3/PERST, port PCIE_Resets.Dig3
GPIOb_10.GPIO6: sheet PCIE2/PERST, port PCIE_Resets.Dig2
GPIOb_11.GPIO1: sheet PCIE4/PERST, port PCIE_Resets.Dig4
NetJ1_PCIE0_20: sheet PCIE0/CLK_Sync, port PCIe_CLK_Syncs.PCIeInt1
NetJ1_PCIE0_43: sheet PCIE0/GPIO0, port PCIE_Ints.PCIeInt1
NetJ1_PCIE1_20: sheet PCIE1/CLK_Sync, port PCIe_CLK_Syncs.PCIeInt2
NetJ1_PCIE1_43: sheet PCIE1/GPIO0, port PCIE_Ints.PCIeInt2
NetJ1_PCIE2_20: sheet PCIE2/CLK_Sync, port PCIe_CLK_Syncs.PCIeInt3
NetJ1_PCIE2_43: sheet PCIE2/GPIO0, port PCIE_Ints.PCIeInt3
NetJ1_PCIE3_20: sheet PCIE3/CLK_Sync, port PCIe_CLK_Syncs.PCIeInt4
NetJ1_PCIE3_43: sheet PCIE3/GPIO0, port PCIE_Ints.PCIeInt4
NetJ1_PCIE4_20: sheet PCIE4/CLK_Sync, port PCIe_CLK_Syncs.PCIeInt5
NetJ1_PCIE4_43: sheet PCIE4/GPIO0, port PCIE_Ints.PCIeInt5
NetR449_2: R449.2 R450.1 ; sheet I2C_Bridge_PCIE/A0
NetR451_2: R451.2 R452.1 ; sheet I2C_Bridge_PCIE/A1
NetR453_2: R453.2 R454.1 ; sheet I2C_Bridge_PCIE/A2

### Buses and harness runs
harness HiSpeedModule_I2C0 = sheet I2C_Bridge_PCIE/I2C2 = sheet Power4HighSpeed/I2C
harness HiSpeedModule_I2C1 = sheet I2C_Bridge_PCIE/I2C1 = sheet PCIE0/I2C
harness HiSpeedModule_I2C2 = sheet I2C_Bridge_PCIE/I2C3 = sheet PCIE1/I2C
harness HiSpeedModule_I2C3 = sheet I2C_Bridge_PCIE/I2C4 = sheet PCIE2/I2C
harness HiSpeedModule_I2C4 = sheet I2C_Bridge_PCIE/I2C0 = sheet PCIE3/I2C
harness HiSpeedModule_I2C5 = sheet I2C_Bridge_PCIE/I2C5 = sheet PCIE4/I2C
harness HiSpeedModule_I2C6 = sheet I2C_Bridge_PCIE/I2C6 = sheet Power4HighSpeed/I2C6
harness HiSpeedModule_I2C7 = sheet I2C_Bridge_PCIE/I2C7 = sheet Power4HighSpeed/I2C7
harness HiSpeedModule_SPI0 = sheet PCIE0/SPI_PCIE = sheet SPI_bridge_PCIe/SPI_Q0
harness HiSpeedModule_SPI1 = sheet PCIE1/SPI_PCIE = sheet SPI_bridge_PCIe/SPI_Q1
harness HiSpeedModule_SPI2 = sheet PCIE2/SPI_PCIE = sheet SPI_bridge_PCIe/SPI_Q2
harness HiSpeedModule_SPI3 = sheet PCIE3/SPI_PCIE = sheet SPI_bridge_PCIe/SPI_Q3
harness HiSpeedModule_SPI4 = sheet PCIE4/SPI_PCIE = sheet SPI_bridge_PCIe/SPI_Q4
harness port I2C_3.3V = sheet I2C_Bridge_PCIE/I2C_3.3V
harness port PCIE_CLK0 = sheet PCIE0/PCIE_CLK
harness port PCIE_CLK1 = sheet PCIE1/PCIE_CLK
harness port PCIE_CLK2 = sheet PCIE2/PCIE_CLK
harness port PCIE_CLK3 = sheet PCIE3/PCIE_CLK
harness port PCIE_CLK4 = sheet PCIE4/PCIE_CLK
harness port PWR_CTRL = sheet Power4HighSpeed/CtrlHiSpeed
harness port PWR_PCIE_Int10 = sheet Power4HighSpeed/PWR_PCIE_Int10
harness port SPI_CTRL = sheet SPI_bridge_PCIe/Ctrl_SPI
harness port SPI_PCIE = sheet SPI_bridge_PCIe/SPI_In
harness port SYNC_0 = sheet PCIE0/FPGA_CLKs
harness port SYNC_1 = sheet PCIE1/FPGA_CLKs
harness port SYNC_2 = sheet PCIE2/FPGA_CLKs
harness port SYNC_3 = sheet PCIE3/FPGA_CLKs
harness port SYNC_4 = sheet PCIE4/FPGA_CLKs
harness sheet Bank 223/Data_0 = sheet PCIE0/Data_0
harness sheet Bank 223/Data_1 = sheet PCIE0/Data_1
harness sheet Bank 223/Data_2 = sheet PCIE1/Data_0
harness sheet Bank 223/Data_3 = sheet PCIE1/Data_1
harness sheet Bank 223/MGMTCLK0 = sheet PCIE0/FPGA_CLK
harness sheet Bank 223/MGMTCLK1 = sheet PCIE1/FPGA_CLK
harness sheet Bank 224/Data_0 = sheet PCIE2/Data_0
harness sheet Bank 224/Data_1 = sheet PCIE2/Data_1
harness sheet Bank 224/Data_2 = sheet PCIE3/Data_0
harness sheet Bank 224/Data_3 = sheet PCIE3/Data_1
harness sheet Bank 224/MGMTCLK0 = sheet PCIE2/FPGA_CLK
harness sheet Bank 224/MGMTCLK1 = sheet PCIE3/FPGA_CLK
harness sheet Bank 225/Data_0 = sheet PCIE4/Data_0
harness sheet Bank 225/Data_1 = sheet PCIE4/Data_1
harness sheet Bank 225/Data_2 = sheet PCIE4/Data_2
harness sheet Bank 225/Data_3 = sheet PCIE4/Data_3
harness sheet Bank 225/MGMTCLK0 = sheet PCIE4/FPGA_CLK

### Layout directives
net class SPI_PCIE_RF_0: (no net found under the mark)
net class SPI_PCIE_RF_1: (no net found under the mark)
net class SPI_PCIE_RF_2: (no net found under the mark)
net class SPI_PCIE_RF_3: (no net found under the mark)
net class SPI_PCIE_RF_4: (no net found under the mark)

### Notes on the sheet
- 0xE2
- I2C0..7 -3.3V
- SPI_PCIE0..4 3.3V
- Napięcie SPI zależy od MIO

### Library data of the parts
R449 R451 R453 = Resistor: as R124 on sheet Ultrascale+_02
R450 R452 R454 = Resistor: as R539 on sheet LTC6952

## Sheet PCIe.SchDoc: PCIe
size A3; Organization: Altium Limited; Address1: L3, 12a Rodborough Rd; Address2: Frenchs Forest; Address3: NSW; Address4: Australia 2086
Used 5 times, as channels HighSpeed/PCIE0, HighSpeed/PCIE1, HighSpeed/PCIE2, HighSpeed/PCIE3, HighSpeed/PCIE4. Parts and nets are listed once, with the designators drawn on the sheet.
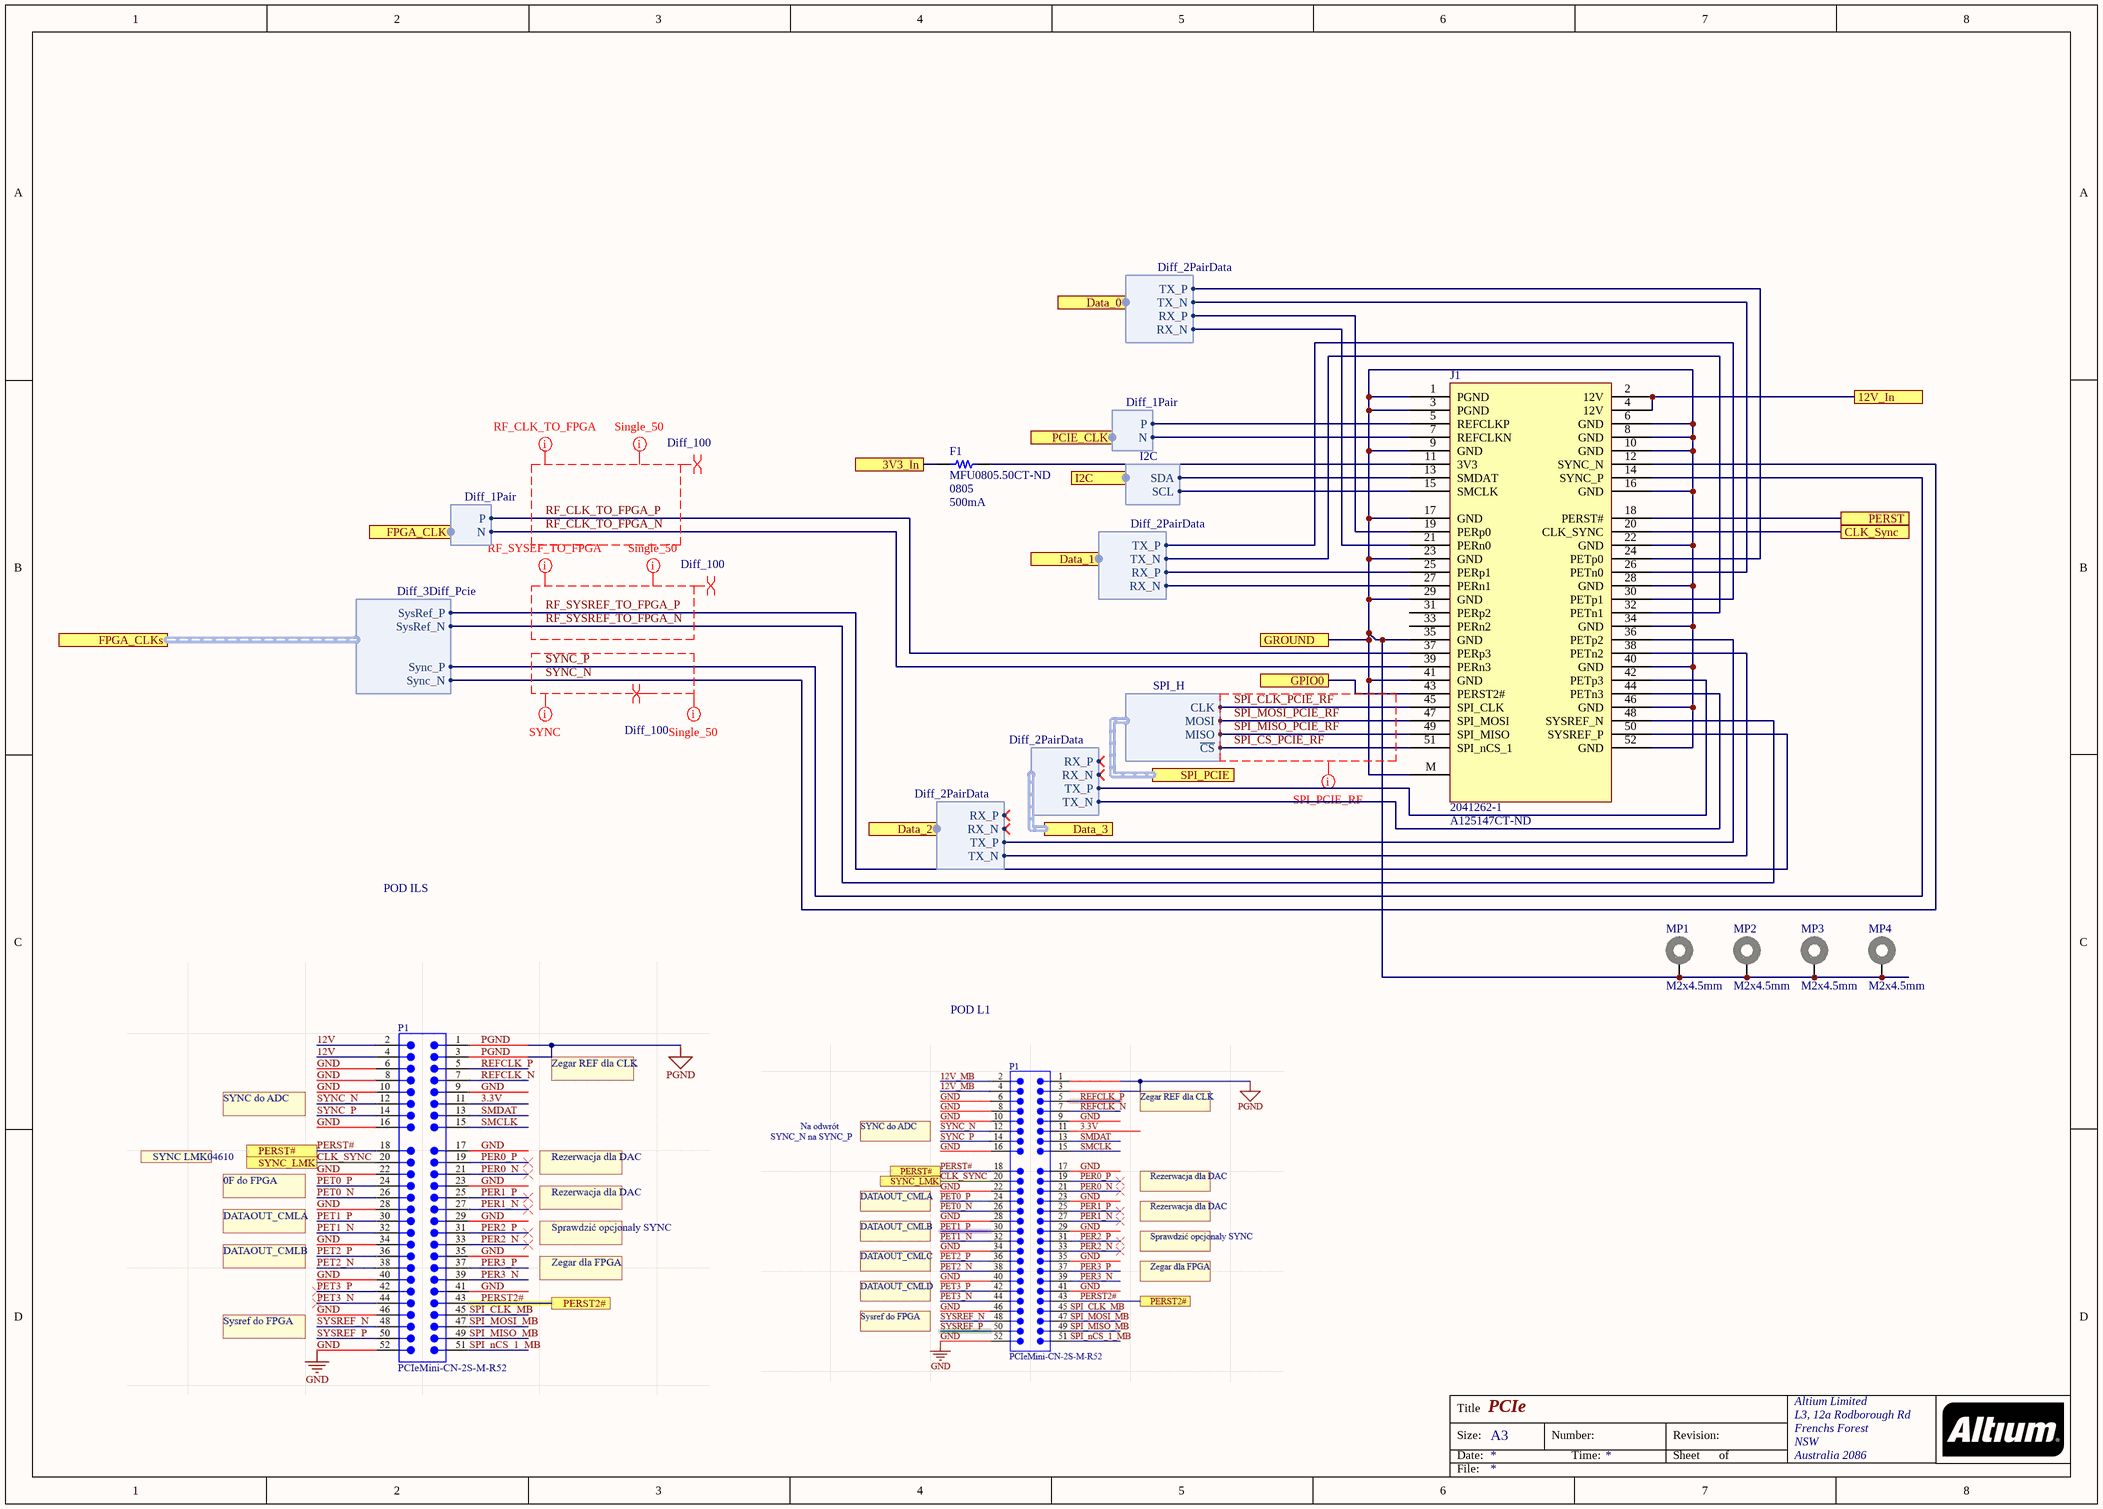
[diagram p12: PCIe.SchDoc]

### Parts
F1  Supplier Part Number 1: MFU0805.50CT-ND  Case Code (Imperial): 0805  Fuse Current: 500mA  [RES 0805/2012 RF]
J1  2041262-1  Supplier Part Number 1: A125147CT-ND  [PCI Express / PCI Connectors Mini PCI-E 6.8H G/F]
MP1  M2x4.5mm  [9774045243 - dual side copper]
MP2  M2x4.5mm  [9774045243 - dual side copper]
MP3  M2x4.5mm  [9774045243 - dual side copper]
MP4  M2x4.5mm  [9774045243 - dual side copper]

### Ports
3V3_In, 12V_In, CLK_Sync, Data_0 (harness Diff_2PairData), Data_1 (harness Diff_2PairData), Data_2 (harness Diff_2PairData), Data_3 (harness Diff_2PairData), FPGA_CLK (harness Diff_1Pair), FPGA_CLKs (harness Diff_3Diff_Pcie), GPIO0, GROUND, I2C (harness I2C), PCIE_CLK (harness Diff_1Pair), PERST, SPI_PCIE (harness SPI_H)

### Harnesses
I2C: SDA, SCL
SPI_H: CLK, MISO, MOSI, ~{CS}
Diff_2PairData: RX_P, RX_N, TX_P, TX_N
Diff_1Pair: N, P
Diff_3Diff_Pcie: SysRef_N, SysRef_P, Sync_P, Sync_N

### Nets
3V3_In: F1.2 ; port 3V3_In
12V_In: J1.2(12V) J1.4(12V) ; port 12V_In
CLK_Sync: J1.20(CLK_SYNC) ; port CLK_Sync
GPIO0: J1.43(PERST2#) ; port GPIO0
GROUND: J1.1(PGND) J1.3(PGND) J1.6(GND) J1.8(GND) J1.9(GND) J1.10(GND) J1.16(GND) J1.17(GND) J1.22(GND) J1.23(GND) J1.28(GND) J1.29(GND) J1.34(GND) J1.35(GND) J1.40(GND) J1.41(GND) J1.46(GND) J1.52(GND) J1.M MP1.1 MP2.1 MP3.1 MP4.1 ; port GROUND
PERST: J1.18(PERST#) ; port PERST
RF_CLK_TO_FPGA_N: J1.39(PERn3) ; port FPGA_CLK.N
RF_CLK_TO_FPGA_P: J1.37(PERp3) ; port FPGA_CLK.P
RF_SYSREF_TO_FPGA_N: J1.48(SYSREF_N) ; port FPGA_CLKs.SysRef_N
RF_SYSREF_TO_FPGA_P: J1.50(SYSREF_P) ; port FPGA_CLKs.SysRef_P
SPI_~{CS}_PCIE_RF: J1.51(SPI_nCS_1) ; port SPI_PCIE.~{CS}
SPI_CLK_PCIE_RF: J1.45(SPI_CLK) ; port SPI_PCIE.CLK
SPI_MISO_PCIE_RF: J1.49(SPI_MISO) ; port SPI_PCIE.MISO
SPI_MOSI_PCIE_RF: J1.47(SPI_MOSI) ; port SPI_PCIE.MOSI
SYNC_N: J1.12(SYNC_N) ; port FPGA_CLKs.Sync_N
SYNC_P: J1.14(SYNC_P) ; port FPGA_CLKs.Sync_P
NetF1_1: F1.1 J1.11(3V3)
NetJ1_5: J1.5(REFCLKP) ; port PCIE_CLK.P
NetJ1_7: J1.7(REFCLKN) ; port PCIE_CLK.N
NetJ1_13: J1.13(SMDAT) ; port I2C.SDA
NetJ1_15: J1.15(SMCLK) ; port I2C.SCL
NetJ1_19: J1.19(PERp0) ; port Data_0.RX_P
NetJ1_21: J1.21(PERn0) ; port Data_0.RX_N
NetJ1_24: J1.24(PETp0) ; port Data_0.TX_P
NetJ1_25: J1.25(PERp1) ; port Data_1.RX_P
NetJ1_26: J1.26(PETn0) ; port Data_0.TX_N
NetJ1_27: J1.27(PERn1) ; port Data_1.RX_N
NetJ1_30: J1.30(PETp1) ; port Data_1.TX_P
NetJ1_32: J1.32(PETn1) ; port Data_1.TX_N
NetJ1_36: J1.36(PETp2) ; port Data_2.TX_P
NetJ1_38: J1.38(PETn2) ; port Data_2.TX_N
NetJ1_42: J1.42(PETp3) ; port Data_3.TX_P
NetJ1_44: J1.44(PETn3) ; port Data_3.TX_N

Not connected (* = marked no-connect by the designer): J1 31(PERp2) 33(PERn2)

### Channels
HighSpeed/PCIE0: designators end in _PCIE0; ports 3V3_In=3V3_RAIL 12V_In=12V_PCIE0_CM CLK_Sync=NetJ1_PCIE0_20 GPIO0=NetJ1_PCIE0_43 GROUND=B503_Ground PERST=GPIOa_02.GPIO0
HighSpeed/PCIE1: designators end in _PCIE1; ports 3V3_In=3V3_RAIL 12V_In=12V_PCIE1_CM CLK_Sync=NetJ1_PCIE1_20 GPIO0=NetJ1_PCIE1_43 GROUND=B503_Ground PERST=GPIOa_11.GPIO1
HighSpeed/PCIE2: designators end in _PCIE2; ports 3V3_In=3V3_RAIL 12V_In=12V_PCIE2_CM CLK_Sync=NetJ1_PCIE2_20 GPIO0=NetJ1_PCIE2_43 GROUND=B503_Ground PERST=GPIOb_10.GPIO6
HighSpeed/PCIE3: designators end in _PCIE3; ports 3V3_In=3V3_RAIL 12V_In=12V_PCIE3_CM CLK_Sync=NetJ1_PCIE3_20 GPIO0=NetJ1_PCIE3_43 GROUND=B503_Ground PERST=GPIOb_02.GPIO2
HighSpeed/PCIE4: designators end in _PCIE4; ports 3V3_In=3V3_RAIL 12V_In=12V_PCIE4_CM CLK_Sync=NetJ1_PCIE4_20 GPIO0=NetJ1_PCIE4_43 GROUND=B503_Ground PERST=GPIOb_11.GPIO1

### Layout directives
mark named RF_CLK_TO_FPGA: RF_CLK_TO_FPGA_N, RF_CLK_TO_FPGA_P
net class RF_SYSEF_TO_FPGA*: RF_SYSREF_TO_FPGA_N, RF_SYSREF_TO_FPGA_P
net class SYNC: SYNC_N, SYNC_P
differential pair; differential pair class Diff_100: RF_CLK_TO_FPGA_N, RF_CLK_TO_FPGA_P, RF_SYSREF_TO_FPGA_N, RF_SYSREF_TO_FPGA_P, SYNC_N, SYNC_P
net class Single_50: RF_CLK_TO_FPGA_N, RF_CLK_TO_FPGA_P, RF_SYSREF_TO_FPGA_N, RF_SYSREF_TO_FPGA_P, SYNC_N, SYNC_P
net class SPI_PCIE_RF: SPI_CLK_PCIE_RF, SPI_MISO_PCIE_RF, SPI_MOSI_PCIE_RF, SPI_~{CS}_PCIE_RF

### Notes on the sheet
- POD ILS
- POD L1

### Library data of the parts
F1 = Resistor: FUSE BOARD MNT 500MA 32VDC 0805; Manufacturer: Vishay; Manufacturer Part Number: MFU0805FF00500P100; DC Cold Resistance: 570mR; Working Voltage: 32V; Fuse Type: Board Mount (Cartridge Style Excluded); Approvals: UL
J1 = 2041262-1: PCI Express / PCI Connectors Mini PCI-E 6.8H G/F; Manufacturer: TE Connectivity AMP; Connector Type: Receptacle; Number of Contacts: 52; High Temperature Housing: Yes; PCB Mount Retention: Without; PCB Mounting Orientation: Horizontal; Stackable: No; Pitch: 0.8mm; Row Spacing: 0.031inch; Stack Height: 0.268inch
MP1-MP4 = 9774045243R: WA-SMSI SMT Steel Spacer, OD4.35mm, M2x4.5mm; Inner Diameter: 2.8mm; Outer Diameter: 4.35mm; Surface: Tin; Thread: M2

## Sheet Bank224.SchDoc: Bank224
size A3; Organization: Altium Limited; Address1: L3, 12a Rodborough Rd; Address2: Frenchs Forest; Address3: NSW; Address4: Australia 2086
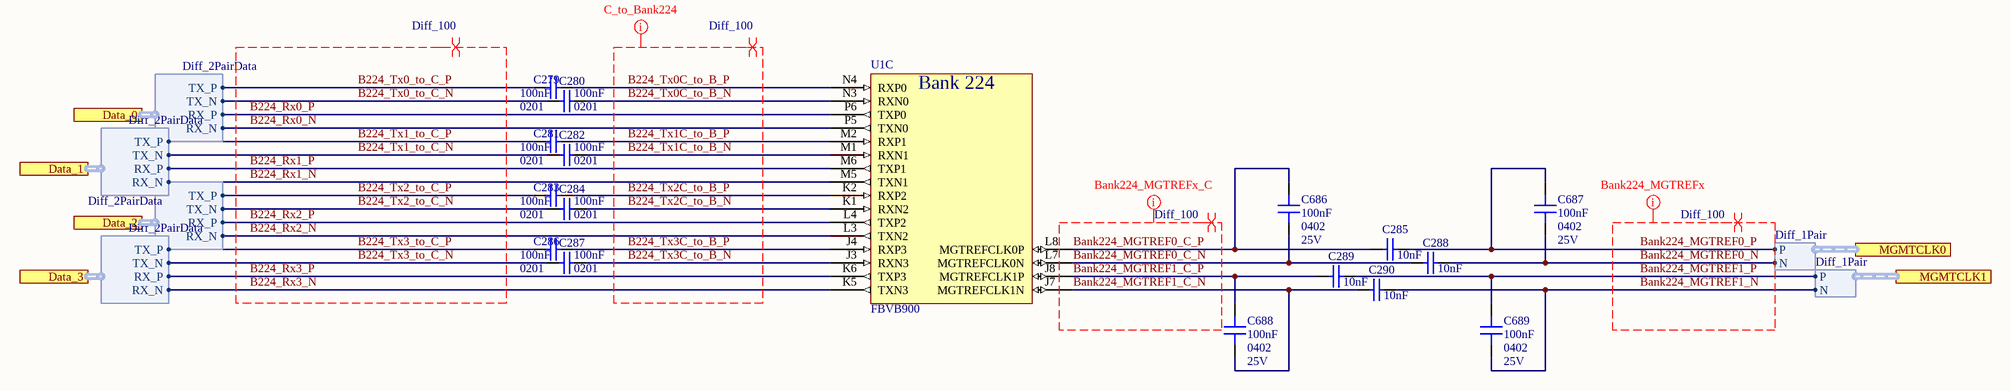
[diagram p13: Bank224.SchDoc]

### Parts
C279  100nF  Case/Package: 0201  [CAP 0201/0603 KK]
C280  100nF  Case/Package: 0201  [CAP 0201/0603 KK]
C281  100nF  Case/Package: 0201  [CAP 0201/0603 KK]
C282  100nF  Case/Package: 0201  [CAP 0201/0603 KK]
C283  100nF  Case/Package: 0201  [CAP 0201/0603 KK]
C284  100nF  Case/Package: 0201  [CAP 0201/0603 KK]
C285  10nF  [CAP 0201/0603 KK]
C286  100nF  Case/Package: 0201  [CAP 0201/0603 KK]
C287  100nF  Case/Package: 0201  [CAP 0201/0603 KK]
C288  10nF  [CAP 0201/0603 KK]
C289  10nF  [CAP 0201/0603 KK]
C290  10nF  [CAP 0201/0603 KK]
C686  100nF  Case/Package: 0402  Voltage Rating: 25V  [CAP 0402/1005 KK]
C687  100nF  Case/Package: 0402  Voltage Rating: 25V  [CAP 0402/1005 KK]
C688  100nF  Case/Package: 0402  Voltage Rating: 25V  [CAP 0402/1005 KK]
C689  100nF  Case/Package: 0402  Voltage Rating: 25V  [CAP 0402/1005 KK]
U1  FBVB900  [FBVB900 XX]  (part C of 23)

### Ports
Data_0 (harness Diff_2PairData), Data_1 (harness Diff_2PairData), Data_2 (harness Diff_2PairData), Data_3 (harness Diff_2PairData), MGMTCLK0 (harness Diff_1Pair), MGMTCLK1 (harness Diff_1Pair)

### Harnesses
Diff_1Pair: P, N
Diff_2PairData: RX_P, RX_N, TX_P, TX_N

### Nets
B224_Rx0_N: U1.P5(TXN0) ; port Data_0.RX_N
B224_Rx0_P: U1.P6(TXP0) ; port Data_0.RX_P
B224_Rx1_N: U1.M5(TXN1) ; port Data_1.RX_N
B224_Rx1_P: U1.M6(TXP1) ; port Data_1.RX_P
B224_Rx2_N: U1.L3(TXN2) ; port Data_2.RX_N
B224_Rx2_P: U1.L4(TXP2) ; port Data_2.RX_P
B224_Rx3_N: U1.K5(TXN3) ; port Data_3.RX_N
B224_Rx3_P: U1.K6(TXP3) ; port Data_3.RX_P
B224_Tx0_to_C_N: C280.1 ; port Data_0.TX_N
B224_Tx0_to_C_P: C279.1 ; port Data_0.TX_P
B224_Tx0C_to_B_N: C280.2 U1.N3(RXN0)
B224_Tx0C_to_B_P: C279.2 U1.N4(RXP0)
B224_Tx1_to_C_N: C282.1 ; port Data_1.TX_N
B224_Tx1_to_C_P: C281.1 ; port Data_1.TX_P
B224_Tx1C_to_B_N: C282.2 U1.M1(RXN1)
B224_Tx1C_to_B_P: C281.2 U1.M2(RXP1)
B224_Tx2_to_C_N: C284.1 ; port Data_2.TX_N
B224_Tx2_to_C_P: C283.1 ; port Data_2.TX_P
B224_Tx2C_to_B_N: C284.2 U1.K1(RXN2)
B224_Tx2C_to_B_P: C283.2 U1.K2(RXP2)
B224_Tx3_to_C_N: C287.1 ; port Data_3.TX_N
B224_Tx3_to_C_P: C286.1 ; port Data_3.TX_P
B224_Tx3C_to_B_N: C287.2 U1.J3(RXN3)
B224_Tx3C_to_B_P: C286.2 U1.J4(RXP3)
Bank224_MGTREF0_C_N: C288.1 C686.2 U1.L7(MGTREFCLK0N)
Bank224_MGTREF0_C_P: C285.1 C686.1 U1.L8(MGTREFCLK0P)
Bank224_MGTREF0_N: C288.2 C687.2 ; port MGMTCLK0.N
Bank224_MGTREF0_P: C285.2 C687.1 ; port MGMTCLK0.P
Bank224_MGTREF1_C_N: C290.1 C688.2 U1.J7(MGTREFCLK1N)
Bank224_MGTREF1_C_P: C289.1 C688.1 U1.J8(MGTREFCLK1P)
Bank224_MGTREF1_N: C290.2 C689.2 ; port MGMTCLK1.N
Bank224_MGTREF1_P: C289.2 C689.1 ; port MGMTCLK1.P

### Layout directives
net class C_to_Bank224: B224_Tx0C_to_B_N, B224_Tx0C_to_B_P, B224_Tx1C_to_B_N, B224_Tx1C_to_B_P, B224_Tx2C_to_B_N, B224_Tx2C_to_B_P, B224_Tx3C_to_B_N, B224_Tx3C_to_B_P
net class Bank224_MGTREFx_C: Bank224_MGTREF0_C_N, Bank224_MGTREF0_C_P, Bank224_MGTREF1_C_N, Bank224_MGTREF1_C_P
differential pair; differential pair class Diff_100: B224_Rx0_N, B224_Rx0_P, B224_Rx1_N, B224_Rx1_P, B224_Rx2_N, B224_Rx2_P, B224_Rx3_N, B224_Rx3_P, B224_Tx0_to_C_N, B224_Tx0_to_C_P, B224_Tx0C_to_B_N, B224_Tx0C_to_B_P, B224_Tx1_to_C_N, B224_Tx1_to_C_P, B224_Tx1C_to_B_N, B224_Tx1C_to_B_P, B224_Tx2_to_C_N, B224_Tx2_to_C_P, B224_Tx2C_to_B_N, B224_Tx2C_to_B_P, B224_Tx3_to_C_N, B224_Tx3_to_C_P, B224_Tx3C_to_B_N, B224_Tx3C_to_B_P, Bank224_MGTREF0_C_N, Bank224_MGTREF0_C_P, Bank224_MGTREF0_N, Bank224_MGTREF0_P, Bank224_MGTREF1_C_N, Bank224_MGTREF1_C_P, Bank224_MGTREF1_N, Bank224_MGTREF1_P
net class Bank224_MGTREFx: Bank224_MGTREF0_N, Bank224_MGTREF0_P, Bank224_MGTREF1_N, Bank224_MGTREF1_P

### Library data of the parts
C279-C284 C286 C287 = Capacitor: CAP CER 0.1UF 16V X5R 0201; Manufacturer: Murata; Manufacturer Part Number: GRM033R61C104ME84D; Tolerance: 20%
C285 C288-C290 = Capacitor: CAP CER 10000PF 16V X7R 0201; Manufacturer: Murata; Manufacturer Part Number: GRM033R71C103KE14D; Tolerance: 10%
C686-C689 = Capacitor: as C54 on sheet LTC6952
U1 = FBVB900: as U1 on sheet Ultrascale+_02

## Sheet Bank225.SchDoc: Bank225
size A3; Organization: Altium Limited; Address1: L3, 12a Rodborough Rd; Address2: Frenchs Forest; Address3: NSW; Address4: Australia 2086
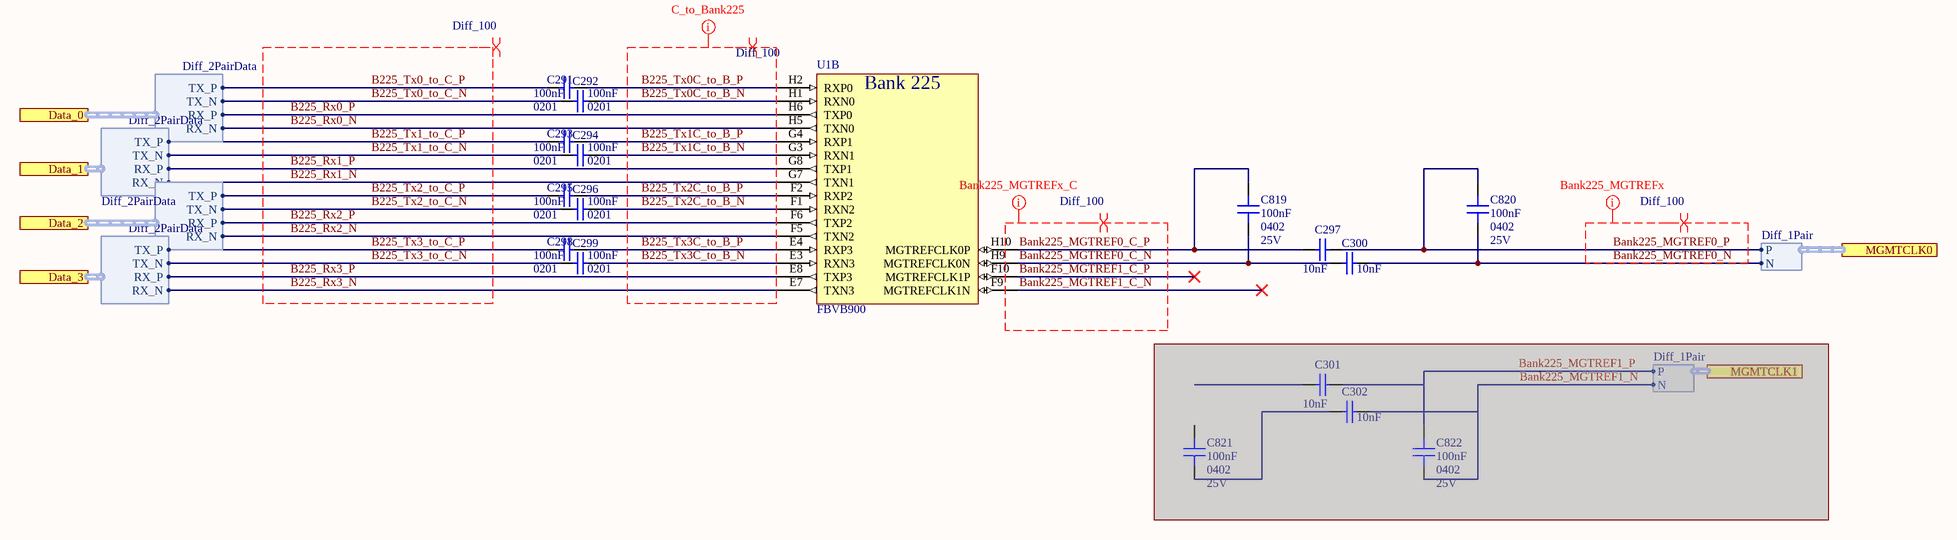
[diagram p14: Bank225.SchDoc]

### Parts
C291  100nF  Case/Package: 0201  [CAP 0201/0603 KK]
C292  100nF  Case/Package: 0201  [CAP 0201/0603 KK]
C293  100nF  Case/Package: 0201  [CAP 0201/0603 KK]
C294  100nF  Case/Package: 0201  [CAP 0201/0603 KK]
C295  100nF  Case/Package: 0201  [CAP 0201/0603 KK]
C296  100nF  Case/Package: 0201  [CAP 0201/0603 KK]
C297  10nF  [CAP 0201/0603 KK]
C298  100nF  Case/Package: 0201  [CAP 0201/0603 KK]
C299  100nF  Case/Package: 0201  [CAP 0201/0603 KK]
C300  10nF  [CAP 0201/0603 KK]
C301  10nF  [CAP 0201/0603 KK]  (masked out: inside a compile mask, not in the netlist)
C302  10nF  [CAP 0201/0603 KK]  (masked out: inside a compile mask, not in the netlist)
C819  100nF  Case/Package: 0402  Voltage Rating: 25V  [CAP 0402/1005 KK]
C820  100nF  Case/Package: 0402  Voltage Rating: 25V  [CAP 0402/1005 KK]
C821  100nF  Case/Package: 0402  Voltage Rating: 25V  [CAP 0402/1005 KK]  (masked out: inside a compile mask, not in the netlist)
C822  100nF  Case/Package: 0402  Voltage Rating: 25V  [CAP 0402/1005 KK]  (masked out: inside a compile mask, not in the netlist)
U1  FBVB900  [FBVB900 XX]  (part B of 23)

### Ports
Data_0 (harness Diff_2PairData), Data_1 (harness Diff_2PairData), Data_2 (harness Diff_2PairData), Data_3 (harness Diff_2PairData), MGMTCLK0 (harness Diff_1Pair), MGMTCLK1 (harness Diff_1Pair)

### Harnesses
Diff_1Pair: P, N
Diff_2PairData: RX_P, RX_N, TX_P, TX_N

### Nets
B225_Rx0_N: U1.H5(TXN0) ; port Data_0.RX_N
B225_Rx0_P: U1.H6(TXP0) ; port Data_0.RX_P
B225_Rx1_N: U1.G7(TXN1) ; port Data_1.RX_N
B225_Rx1_P: U1.G8(TXP1) ; port Data_1.RX_P
B225_Rx2_N: U1.F5(TXN2) ; port Data_2.RX_N
B225_Rx2_P: U1.F6(TXP2) ; port Data_2.RX_P
B225_Rx3_N: U1.E7(TXN3) ; port Data_3.RX_N
B225_Rx3_P: U1.E8(TXP3) ; port Data_3.RX_P
B225_Tx0_to_C_N: C292.1 ; port Data_0.TX_N
B225_Tx0_to_C_P: C291.1 ; port Data_0.TX_P
B225_Tx0C_to_B_N: C292.2 U1.H1(RXN0)
B225_Tx0C_to_B_P: C291.2 U1.H2(RXP0)
B225_Tx1_to_C_N: C294.1 ; port Data_1.TX_N
B225_Tx1_to_C_P: C293.1 ; port Data_1.TX_P
B225_Tx1C_to_B_N: C294.2 U1.G3(RXN1)
B225_Tx1C_to_B_P: C293.2 U1.G4(RXP1)
B225_Tx2_to_C_N: C296.1 ; port Data_2.TX_N
B225_Tx2_to_C_P: C295.1 ; port Data_2.TX_P
B225_Tx2C_to_B_N: C296.2 U1.F1(RXN2)
B225_Tx2C_to_B_P: C295.2 U1.F2(RXP2)
B225_Tx3_to_C_N: C299.1 ; port Data_3.TX_N
B225_Tx3_to_C_P: C298.1 ; port Data_3.TX_P
B225_Tx3C_to_B_N: C299.2 U1.E3(RXN3)
B225_Tx3C_to_B_P: C298.2 U1.E4(RXP3)
Bank225_MGTREF0_C_N: C300.1 C819.2 U1.H9(MGTREFCLK0N)
Bank225_MGTREF0_C_P: C297.1 C819.1 U1.H10(MGTREFCLK0P)
Bank225_MGTREF0_N: C300.2 C820.2 ; port MGMTCLK0.N
Bank225_MGTREF0_P: C297.2 C820.1 ; port MGMTCLK0.P
Bank225_MGTREF1_C_N: U1.F9(MGTREFCLK1N)
Bank225_MGTREF1_C_P: U1.F10(MGTREFCLK1P)

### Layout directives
net class C_to_Bank225: B225_Tx0C_to_B_N, B225_Tx0C_to_B_P, B225_Tx1C_to_B_N, B225_Tx1C_to_B_P, B225_Tx2C_to_B_N, B225_Tx2C_to_B_P, B225_Tx3C_to_B_N, B225_Tx3C_to_B_P
net class Bank225_MGTREFx_C: Bank225_MGTREF0_C_N, Bank225_MGTREF0_C_P, Bank225_MGTREF1_C_N, Bank225_MGTREF1_C_P
differential pair; differential pair class Diff_100: B225_Rx0_N, B225_Rx0_P, B225_Rx1_N, B225_Rx1_P, B225_Rx2_N, B225_Rx2_P, B225_Rx3_N, B225_Rx3_P, B225_Tx0_to_C_N, B225_Tx0_to_C_P, B225_Tx0C_to_B_N, B225_Tx0C_to_B_P, B225_Tx1_to_C_N, B225_Tx1_to_C_P, B225_Tx1C_to_B_N, B225_Tx1C_to_B_P, B225_Tx2_to_C_N, B225_Tx2_to_C_P, B225_Tx2C_to_B_N, B225_Tx2C_to_B_P, B225_Tx3_to_C_N, B225_Tx3_to_C_P, B225_Tx3C_to_B_N, B225_Tx3C_to_B_P, Bank225_MGTREF0_C_N, Bank225_MGTREF0_C_P, Bank225_MGTREF0_N, Bank225_MGTREF0_P, Bank225_MGTREF1_C_N, Bank225_MGTREF1_C_P
net class Bank225_MGTREFx: Bank225_MGTREF0_N, Bank225_MGTREF0_P

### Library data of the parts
C291-C296 C298 C299 = Capacitor: as C279 on sheet Bank224
C297 C300-C302 = Capacitor: as C285 on sheet Bank224
C819-C822 = Capacitor: as C54 on sheet LTC6952
U1 = FBVB900: as U1 on sheet Ultrascale+_02

## Sheet Bank223.SchDoc: Bank223
size A3; Organization: Altium Limited; Address1: L3, 12a Rodborough Rd; Address2: Frenchs Forest; Address3: NSW; Address4: Australia 2086
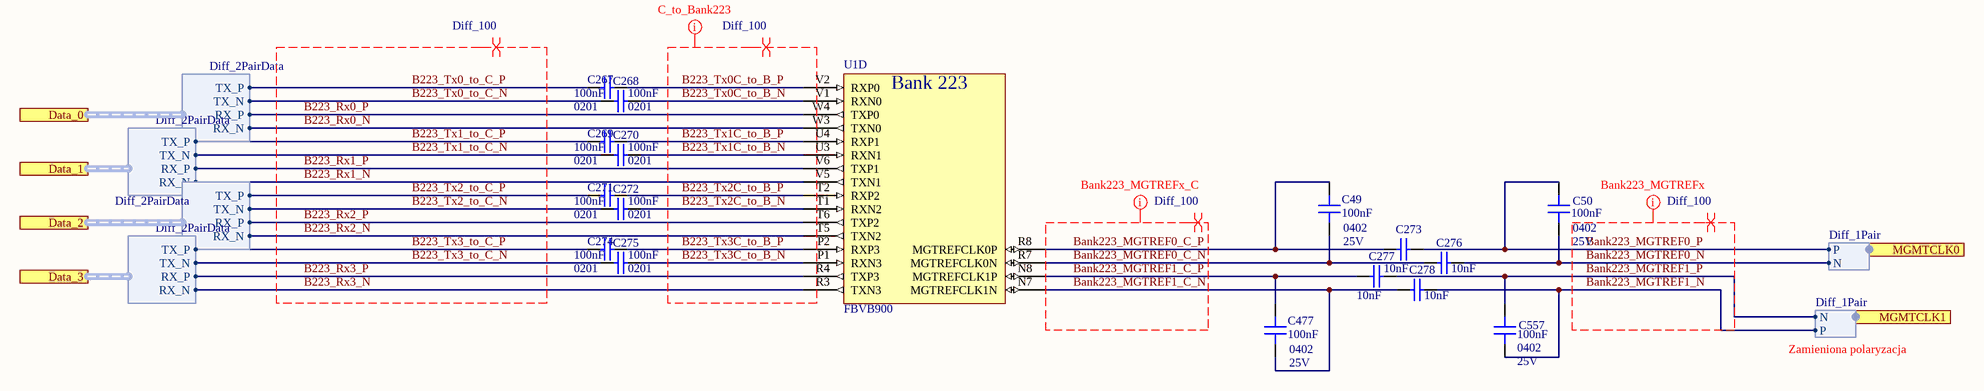
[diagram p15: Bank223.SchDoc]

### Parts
(Parts that share a designator on the sheet are numbered #1, #2 ... from top to bottom, then left to right.)
C49  100nF  Case/Package: 0402  Voltage Rating: 25V  [CAP 0402/1005 KK]
C50  100nF  Case/Package: 0402  Voltage Rating: 25V  [CAP 0402/1005 KK]
C267  100nF  Case/Package: 0201  [CAP 0201/0603 KK]
C268  100nF  Case/Package: 0201  [CAP 0201/0603 KK]
C269  100nF  Case/Package: 0201  [CAP 0201/0603 KK]
C270  100nF  Case/Package: 0201  [CAP 0201/0603 KK]
C271  100nF  Case/Package: 0201  [CAP 0201/0603 KK]
C272  100nF  Case/Package: 0201  [CAP 0201/0603 KK]
C273  10nF  [CAP 0201/0603 KK]
C274  100nF  Case/Package: 0201  [CAP 0201/0603 KK]
C275  100nF  Case/Package: 0201  [CAP 0201/0603 KK]
C276  10nF  [CAP 0201/0603 KK]
C277  10nF  [CAP 0201/0603 KK]
C278  10nF  [CAP 0201/0603 KK]
C477#1  100nF  Case/Package: 0402  Voltage Rating: 25V  [CAP 0402/1005 KK]
C557  100nF  Case/Package: 0402  Voltage Rating: 25V  [CAP 0402/1005 KK]
U1  FBVB900  [FBVB900 XX]  (part D of 23)

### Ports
Data_0 (harness Diff_2PairData), Data_1 (harness Diff_2PairData), Data_2 (harness Diff_2PairData), Data_3 (harness Diff_2PairData), MGMTCLK0 (harness Diff_1Pair), MGMTCLK1 (harness Diff_1Pair)

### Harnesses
Diff_1Pair: P, N
Diff_2PairData: RX_P, RX_N, TX_P, TX_N

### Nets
B223_Rx0_N: U1.W3(TXN0) ; port Data_0.RX_N
B223_Rx0_P: U1.W4(TXP0) ; port Data_0.RX_P
B223_Rx1_N: U1.V5(TXN1) ; port Data_1.RX_N
B223_Rx1_P: U1.V6(TXP1) ; port Data_1.RX_P
B223_Rx2_N: U1.T5(TXN2) ; port Data_2.RX_N
B223_Rx2_P: U1.T6(TXP2) ; port Data_2.RX_P
B223_Rx3_N: U1.R3(TXN3) ; port Data_3.RX_N
B223_Rx3_P: U1.R4(TXP3) ; port Data_3.RX_P
B223_Tx0_to_C_N: C268.1 ; port Data_0.TX_N
B223_Tx0_to_C_P: C267.1 ; port Data_0.TX_P
B223_Tx0C_to_B_N: C268.2 U1.V1(RXN0)
B223_Tx0C_to_B_P: C267.2 U1.V2(RXP0)
B223_Tx1_to_C_N: C270.1 ; port Data_1.TX_N
B223_Tx1_to_C_P: C269.1 ; port Data_1.TX_P
B223_Tx1C_to_B_N: C270.2 U1.U3(RXN1)
B223_Tx1C_to_B_P: C269.2 U1.U4(RXP1)
B223_Tx2_to_C_N: C272.1 ; port Data_2.TX_N
B223_Tx2_to_C_P: C271.1 ; port Data_2.TX_P
B223_Tx2C_to_B_N: C272.2 U1.T1(RXN2)
B223_Tx2C_to_B_P: C271.2 U1.T2(RXP2)
B223_Tx3_to_C_N: C275.1 ; port Data_3.TX_N
B223_Tx3_to_C_P: C274.1 ; port Data_3.TX_P
B223_Tx3C_to_B_N: C275.2 U1.P1(RXN3)
B223_Tx3C_to_B_P: C274.2 U1.P2(RXP3)
Bank223_MGTREF0_C_N: C49.1 C276.1 U1.R7(MGTREFCLK0N)
Bank223_MGTREF0_C_P: C49.2 C273.1 U1.R8(MGTREFCLK0P)
Bank223_MGTREF0_N: C50.1 C276.2 ; port MGMTCLK0.N
Bank223_MGTREF0_P: C50.2 C273.2 ; port MGMTCLK0.P
Bank223_MGTREF1_C_N: C278.1 C477#1.1 U1.N7(MGTREFCLK1N)
Bank223_MGTREF1_C_P: C277.1 C477#1.2 U1.N8(MGTREFCLK1P)
Bank223_MGTREF1_N: C278.2 C557.1 ; port MGMTCLK1.P
Bank223_MGTREF1_P: C277.2 C557.2 ; port MGMTCLK1.N

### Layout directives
differential pair; differential pair class Diff_100: B223_Rx0_N, B223_Rx0_P, B223_Rx1_N, B223_Rx1_P, B223_Rx2_N, B223_Rx2_P, B223_Rx3_N, B223_Rx3_P, B223_Tx0_to_C_N, B223_Tx0_to_C_P, B223_Tx0C_to_B_N, B223_Tx0C_to_B_P, B223_Tx1_to_C_N, B223_Tx1_to_C_P, B223_Tx1C_to_B_N, B223_Tx1C_to_B_P, B223_Tx2_to_C_N, B223_Tx2_to_C_P, B223_Tx2C_to_B_N, B223_Tx2C_to_B_P, B223_Tx3_to_C_N, B223_Tx3_to_C_P, B223_Tx3C_to_B_N, B223_Tx3C_to_B_P, Bank223_MGTREF0_C_N, Bank223_MGTREF0_C_P, Bank223_MGTREF0_N, Bank223_MGTREF0_P, Bank223_MGTREF1_C_N, Bank223_MGTREF1_C_P, Bank223_MGTREF1_N, Bank223_MGTREF1_P
net class C_to_Bank223: B223_Tx0C_to_B_N, B223_Tx0C_to_B_P, B223_Tx1C_to_B_N, B223_Tx1C_to_B_P, B223_Tx2C_to_B_N, B223_Tx2C_to_B_P, B223_Tx3C_to_B_N, B223_Tx3C_to_B_P
net class Bank223_MGTREFx_C: Bank223_MGTREF0_C_N, Bank223_MGTREF0_C_P, Bank223_MGTREF1_C_N, Bank223_MGTREF1_C_P
net class Bank223_MGTREFx: Bank223_MGTREF0_N, Bank223_MGTREF0_P, Bank223_MGTREF1_N, Bank223_MGTREF1_P

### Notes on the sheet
- Zamieniona polaryzacja

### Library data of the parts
C49 C50 C477#1 C557 = Capacitor: as C54 on sheet LTC6952
C267-C272 C274 C275 = Capacitor: as C279 on sheet Bank224
C273 C276-C278 = Capacitor: as C285 on sheet Bank224
U1 = FBVB900: as U1 on sheet Ultrascale+_02

## Sheet I2C_Bridge.SchDoc: I2C Bridge
size A4; DrawnBy: MrozW; Organization: Altium Limited; Address1: L3, 12a Rodborough Rd; Address2: Frenchs Forest; Address3: NSW; Address4: Australia 2086
Used 3 times, as channels HighSpeed/I2C_Bridge_PCIE, Ext_GPIO/I2C_Bridge_GPIO, SFP_Group+IMU/I2C_Bridge_SFP. Parts and nets are listed once, with the designators drawn on the sheet.
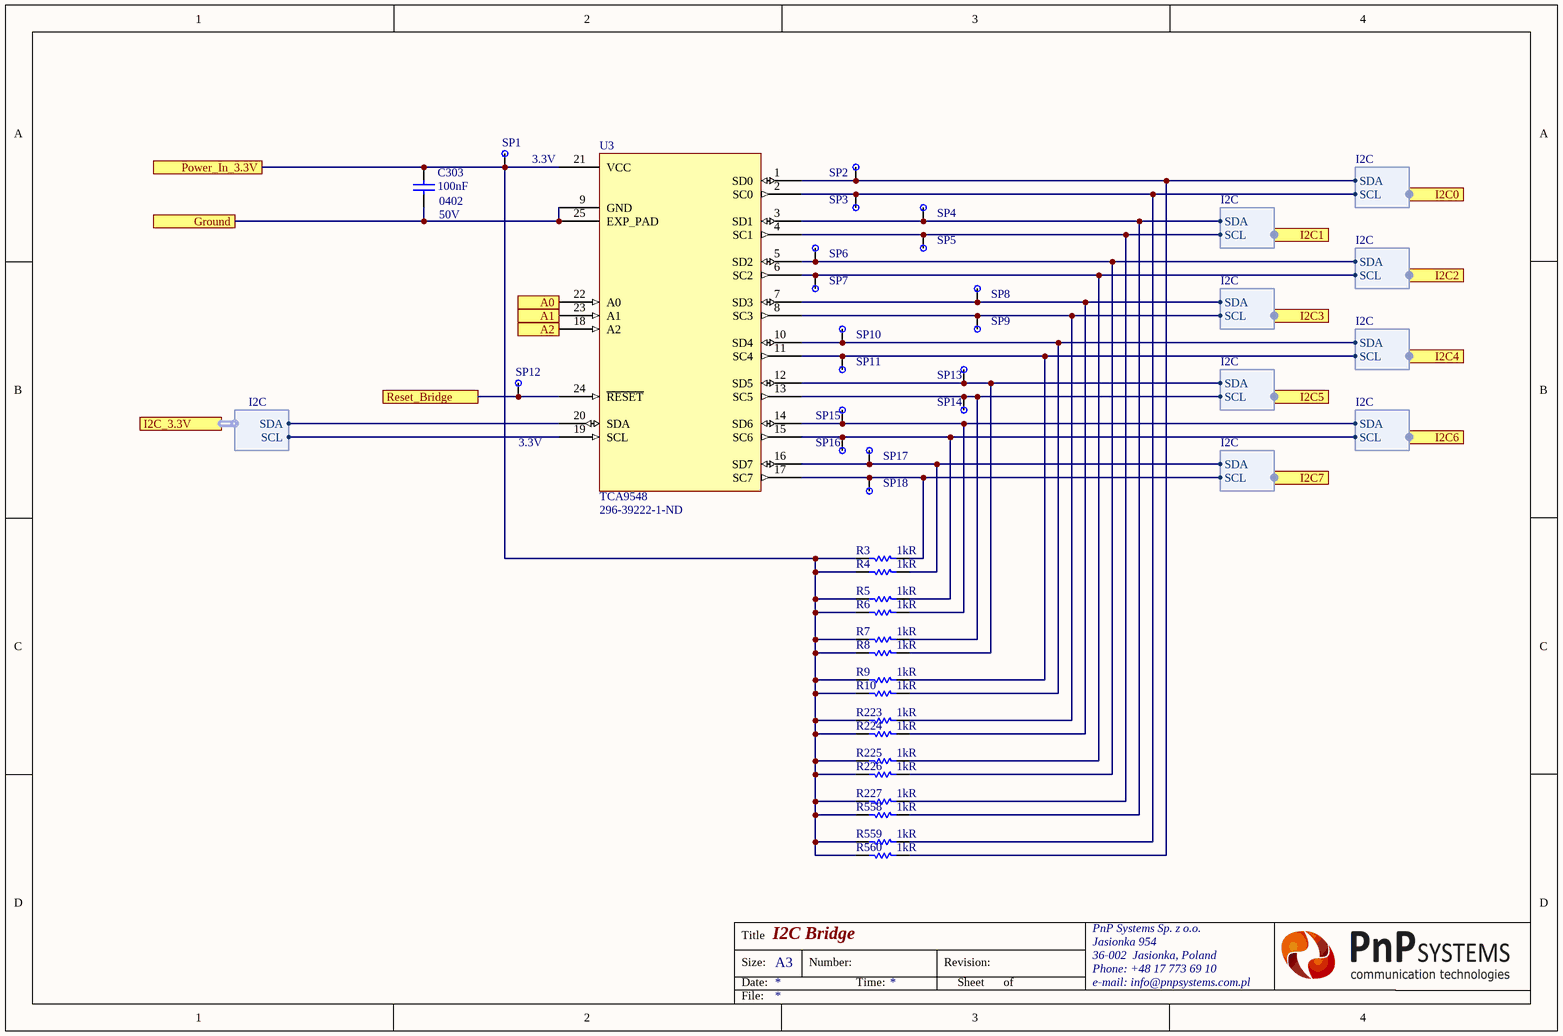
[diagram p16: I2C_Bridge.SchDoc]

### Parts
C303  100nF  Case Code (Imperial): 0402  Voltage: 50V  [CAP 0402/1005 KK]
R3  1kR  [RES 0402/1005 RF KK]
R4  1kR  [RES 0402/1005 RF KK]
R5  1kR  [RES 0402/1005 RF KK]
R6  1kR  [RES 0402/1005 RF KK]
R7  1kR  [RES 0402/1005 RF KK]
R8  1kR  [RES 0402/1005 RF KK]
R9  1kR  [RES 0402/1005 RF KK]
R10  1kR  [RES 0402/1005 RF KK]
R223  1kR  [RES 0402/1005 RF KK]
R224  1kR  [RES 0402/1005 RF KK]
R225  1kR  [RES 0402/1005 RF KK]
R226  1kR  [RES 0402/1005 RF KK]
R227  1kR  [RES 0402/1005 RF KK]
R558  1kR  [RES 0402/1005 RF KK]
R559  1kR  [RES 0402/1005 RF KK]
R560  1kR  [RES 0402/1005 RF KK]
SP1  SP  [MeasureTP]  (value not drawn)
SP2  SP  [MeasureTP]  (value not drawn)
SP3  SP  [MeasureTP]  (value not drawn)
SP4  SP  [MeasureTP]  (value not drawn)
SP5  SP  [MeasureTP]  (value not drawn)
SP6  SP  [MeasureTP]  (value not drawn)
SP7  SP  [MeasureTP]  (value not drawn)
SP8  SP  [MeasureTP]  (value not drawn)
SP9  SP  [MeasureTP]  (value not drawn)
SP10  SP  [MeasureTP]  (value not drawn)
SP11  SP  [MeasureTP]  (value not drawn)
SP12  SP  [MeasureTP]  (value not drawn)
SP13  SP  [MeasureTP]  (value not drawn)
SP14  SP  [MeasureTP]  (value not drawn)
SP15  SP  [MeasureTP]  (value not drawn)
SP16  SP  [MeasureTP]  (value not drawn)
SP17  SP  [MeasureTP]  (value not drawn)
SP18  SP  [MeasureTP]  (value not drawn)
U3  TCA9548  Supplier Part Number 1: 296-39222-1-ND  [TCA9548]

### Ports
A0, A1, A2, Ground, I2C0 (harness I2C), I2C1 (harness I2C), I2C2 (harness I2C), I2C3 (harness I2C), I2C4 (harness I2C), I2C5 (harness I2C), I2C6 (harness I2C), I2C7 (harness I2C), I2C_3.3V (harness I2C), Power_In_3.3V, Reset_Bridge

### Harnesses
I2C: SDA, SCL

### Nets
A0: U3.22(A0) ; port A0
A1: U3.23(A1) ; port A1
A2: U3.18(A2) ; port A2
Ground: C303.1 U3.9(GND) U3.25(EXP_PAD) ; port Ground
Power_In_3.3V: C303.2 R3.1 R4.1 R5.1 R6.1 R7.1 R8.1 R9.1 R10.1 R223.1 R224.1 R225.1 R226.1 R227.1 R558.1 R559.1 R560.1 SP1.1 U3.21(VCC) ; port Power_In_3.3V
Reset_Bridge: SP12.1 U3.24(~{RESET}) ; port Reset_Bridge
NetR3_2: R3.2 SP18.1 U3.17(SC7) ; port I2C7.SCL
NetR4_2: R4.2 SP17.1 U3.16(SD7) ; port I2C7.SDA
NetR5_2: R5.2 SP16.1 U3.15(SC6) ; port I2C6.SCL
NetR6_2: R6.2 SP15.1 U3.14(SD6) ; port I2C6.SDA
NetR7_2: R7.2 SP14.1 U3.13(SC5) ; port I2C5.SCL
NetR8_2: R8.2 SP13.1 U3.12(SD5) ; port I2C5.SDA
NetR9_2: R9.2 SP11.1 U3.11(SC4) ; port I2C4.SCL
NetR10_2: R10.2 SP10.1 U3.10(SD4) ; port I2C4.SDA
NetR223_2: R223.2 SP9.1 U3.8(SC3) ; port I2C3.SCL
NetR224_2: R224.2 SP8.1 U3.7(SD3) ; port I2C3.SDA
NetR225_2: R225.2 SP7.1 U3.6(SC2) ; port I2C2.SCL
NetR226_2: R226.2 SP6.1 U3.5(SD2) ; port I2C2.SDA
NetR227_2: R227.2 SP5.1 U3.4(SC1) ; port I2C1.SCL
NetR558_2: R558.2 SP4.1 U3.3(SD1) ; port I2C1.SDA
NetR559_2: R559.2 SP3.1 U3.2(SC0) ; port I2C0.SCL
NetR560_2: R560.2 SP2.1 U3.1(SD0) ; port I2C0.SDA
NetU3_19: U3.19(SCL) ; port I2C_3.3V.SCL
NetU3_20: U3.20(SDA) ; port I2C_3.3V.SDA

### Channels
HighSpeed/I2C_Bridge_PCIE: designators end in _I2C_Bridge_PCIE; ports A0=NetR449_2 A1=NetR451_2 A2=NetR453_2 Ground=B503_Ground Power_In_3.3V=3V3_RAIL Reset_Bridge=GPIOb_02.GPIO0
Ext_GPIO/I2C_Bridge_GPIO: designators end in _I2C_Bridge_GPIO; ports A0=NetR241_2 A1=NetR243_2 A2=NetR281_2 Ground=B503_Ground Power_In_3.3V=3V3_RAIL Reset_Bridge=NetSP12_I2C_Bridge_GPIO_1
SFP_Group+IMU/I2C_Bridge_SFP: designators end in _I2C_Bridge_SFP; ports A0=NetR469_2 A1=NetR471_2 A2=NetR473_2 Ground=B503_Ground Power_In_3.3V=3V3_RAIL Reset_Bridge=RST_brigde

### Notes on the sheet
- 3.3V

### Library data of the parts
C303 = Capacitor: CAP CER 0.1UF 50V X5R 0402; Manufacturer: Murata; Manufacturer Part Number: GRM155R61H104KE14D; Dielectric Material: Ceramic; Dissipation Factor: 0.025%; Tolerance: 10%
R3-R10 R223-R227 R558-R560 = Resistor: as R124 on sheet Ultrascale+_02
U3 = TCA9548: 8X I2C Switch; Manufacturer: Texas Instruments; Manufacturer Part Number: TCA9548ARGER; Max Supply Voltage: 5.5V; Min Supply Voltage: 1.65V; On-State Resistance: 70R; Max Supply Current: 80uA; Supply Type: Single; Independent Circuits: 1; Propagation Delay: 1ns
